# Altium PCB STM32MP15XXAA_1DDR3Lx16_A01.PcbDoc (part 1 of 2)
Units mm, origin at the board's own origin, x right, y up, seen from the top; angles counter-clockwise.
Board outline 86 x 120 mm, 6 copper layers (Top Layer, Signal Layer 1, Signal Layer 2, Signal Layer 3, Signal Layer 4, Bottom Layer), stack 1.556 mm thick; 100 components, 91 nets, 936 pads, 390 vias.
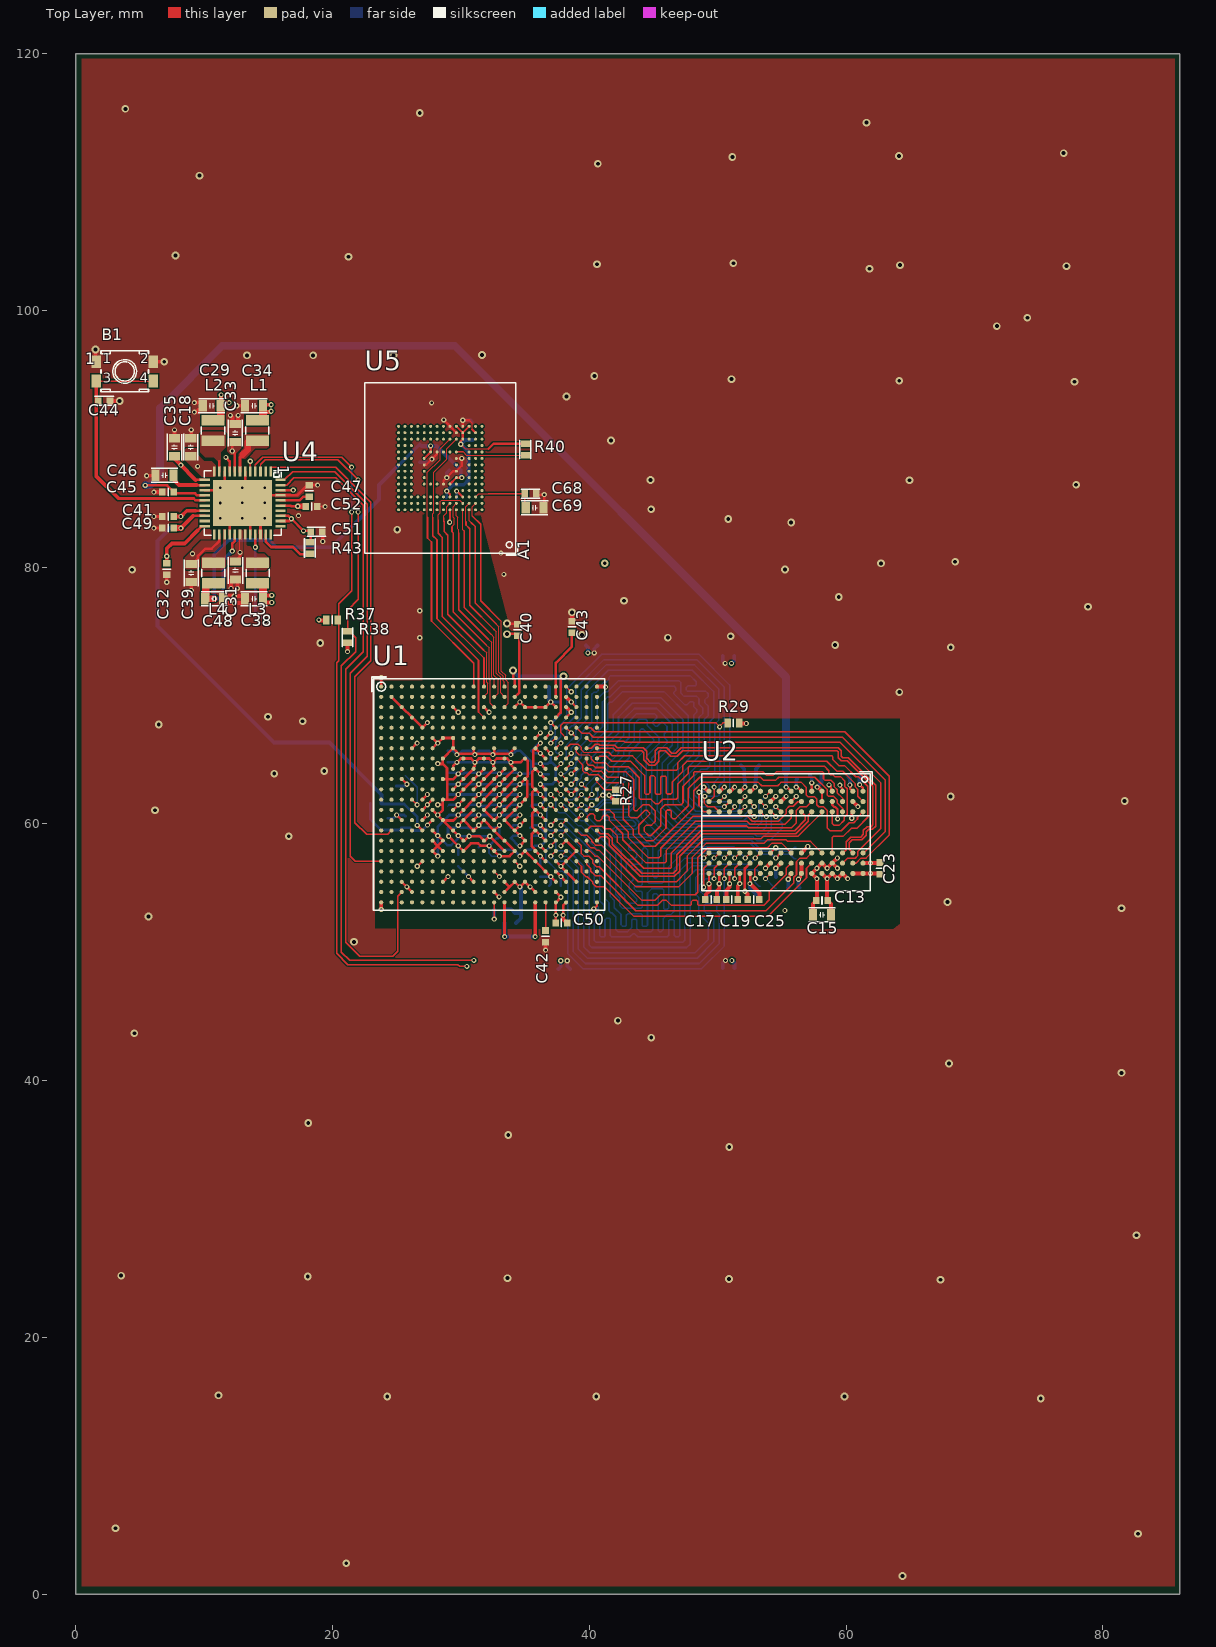
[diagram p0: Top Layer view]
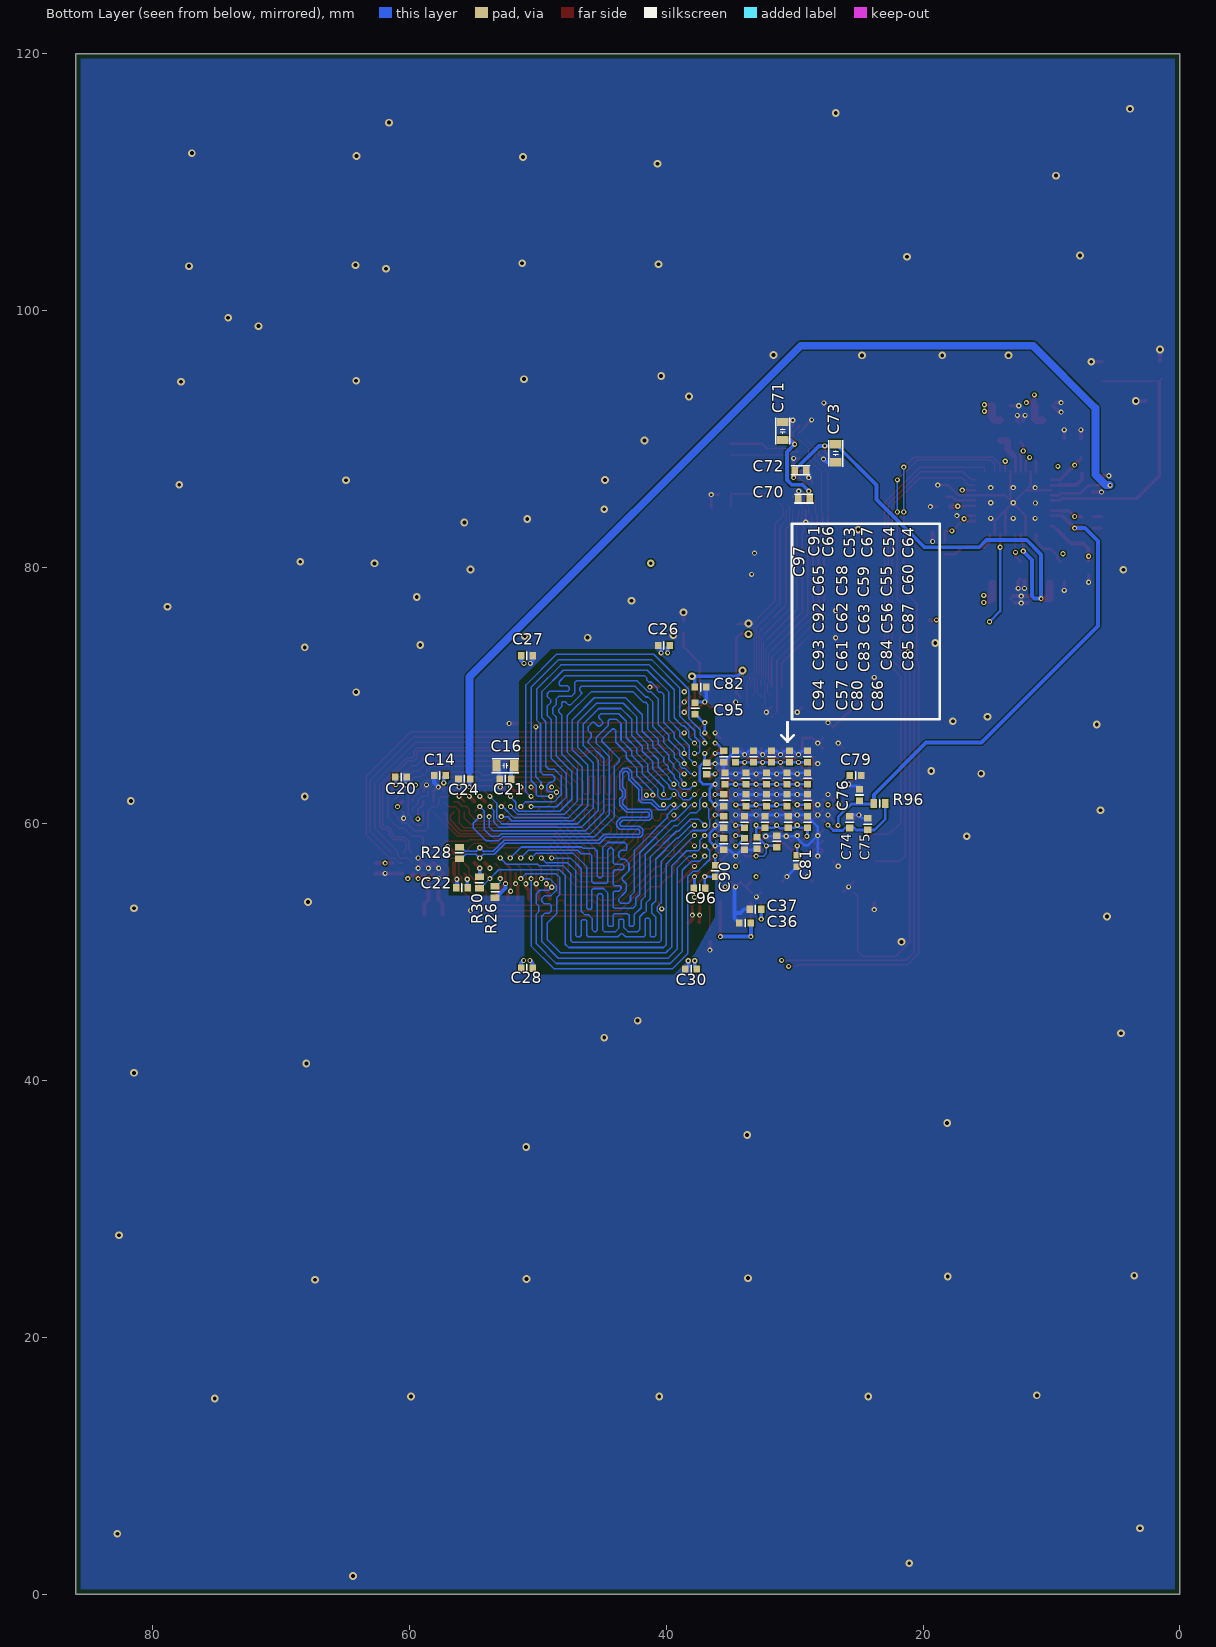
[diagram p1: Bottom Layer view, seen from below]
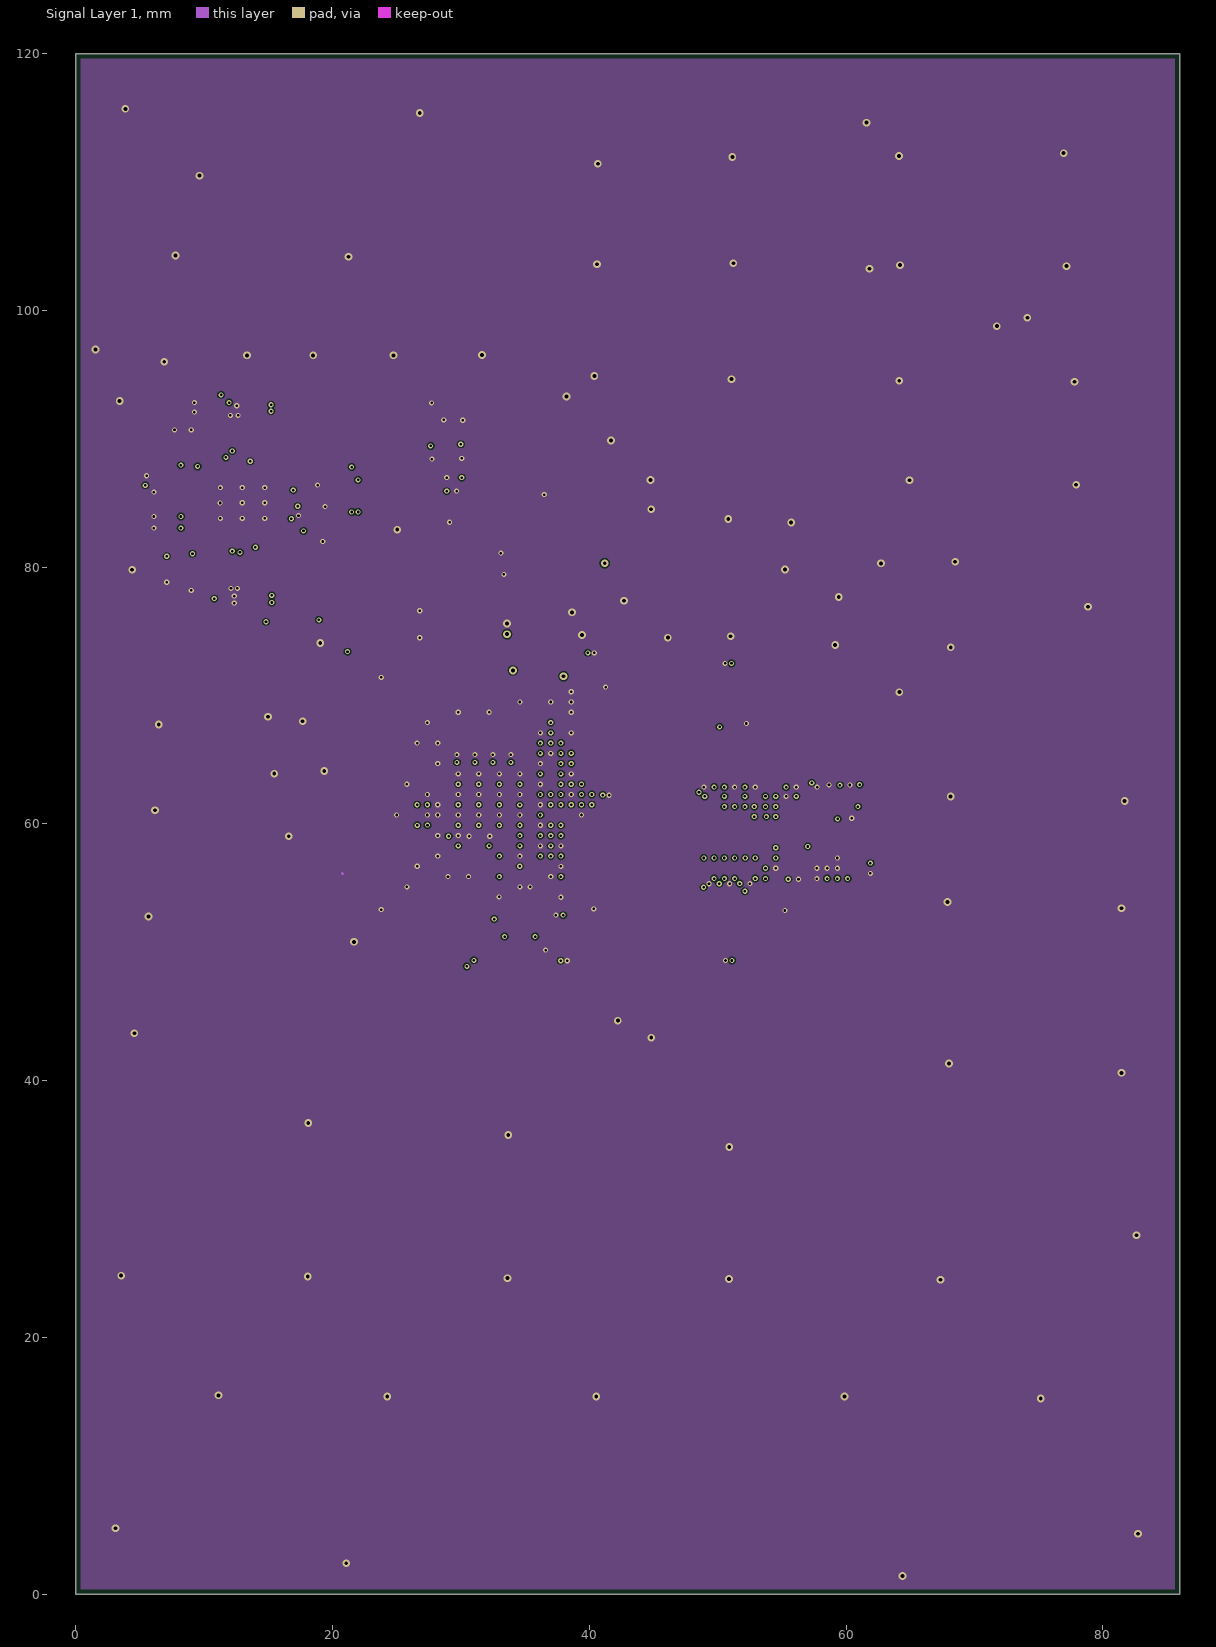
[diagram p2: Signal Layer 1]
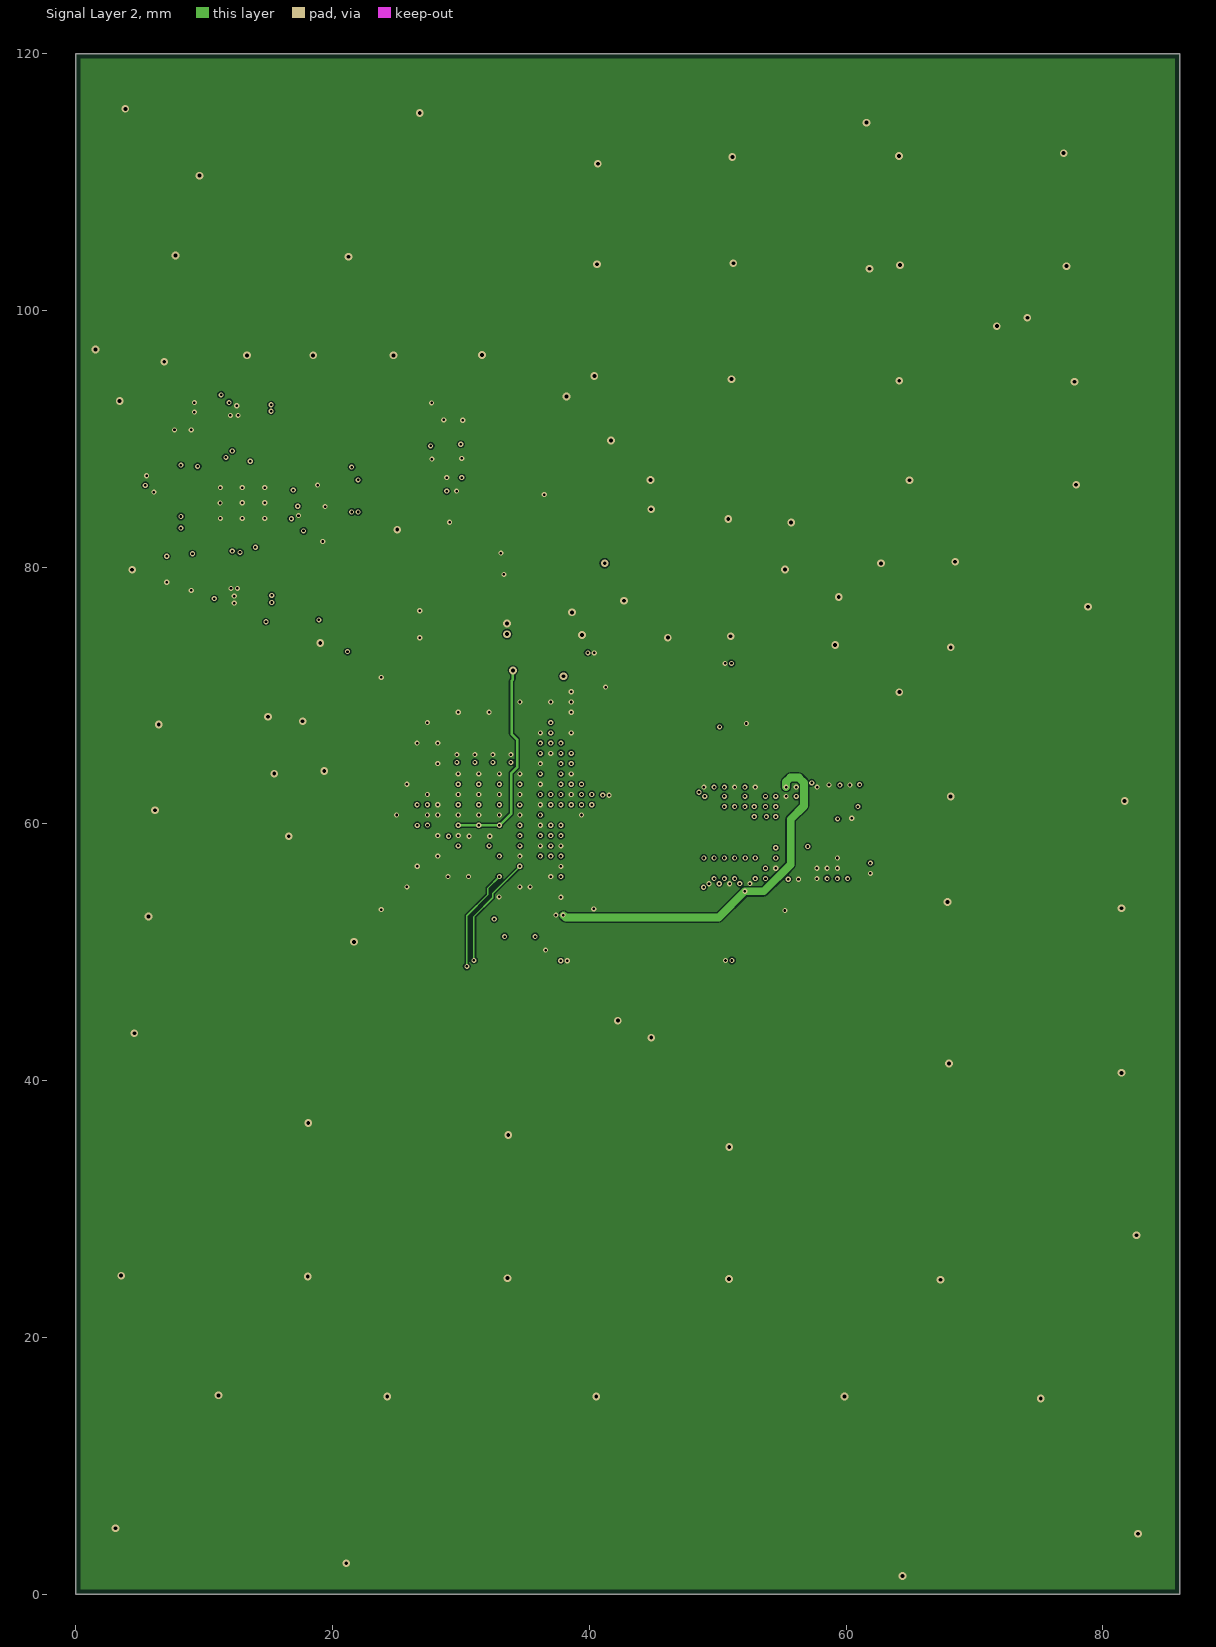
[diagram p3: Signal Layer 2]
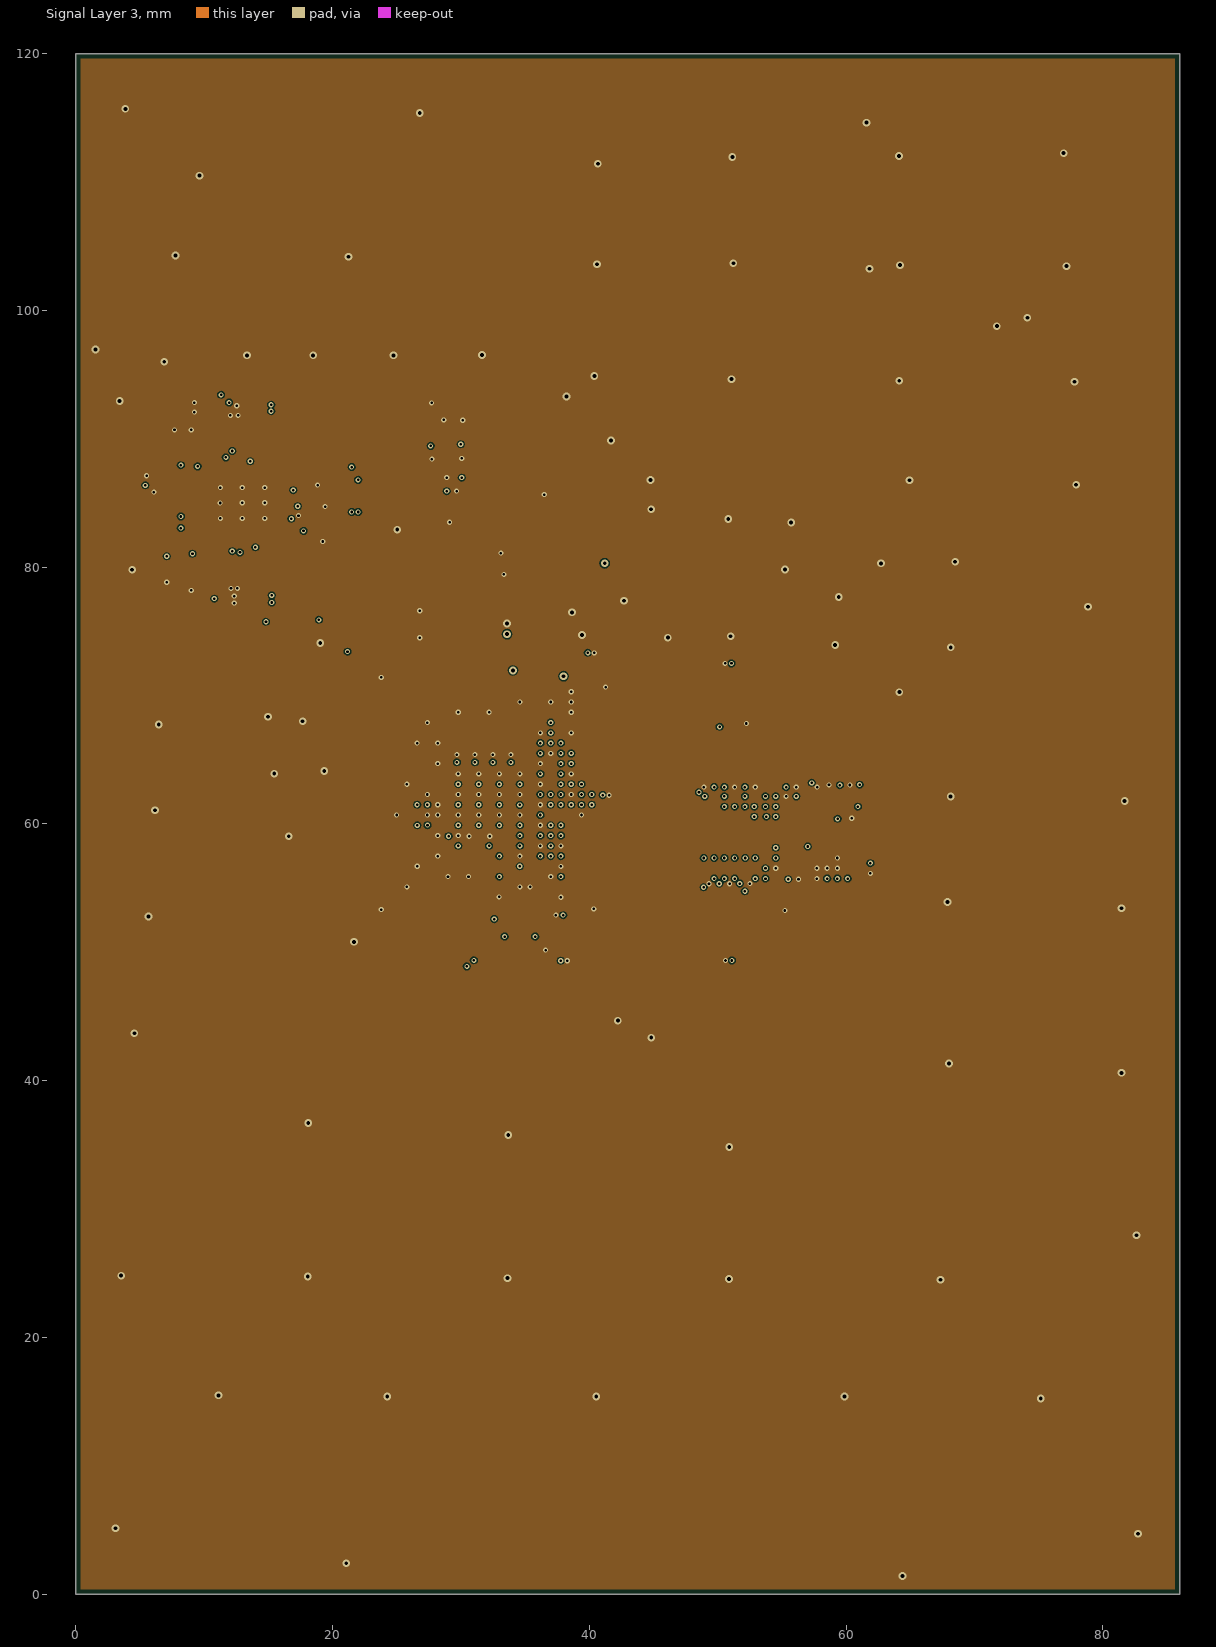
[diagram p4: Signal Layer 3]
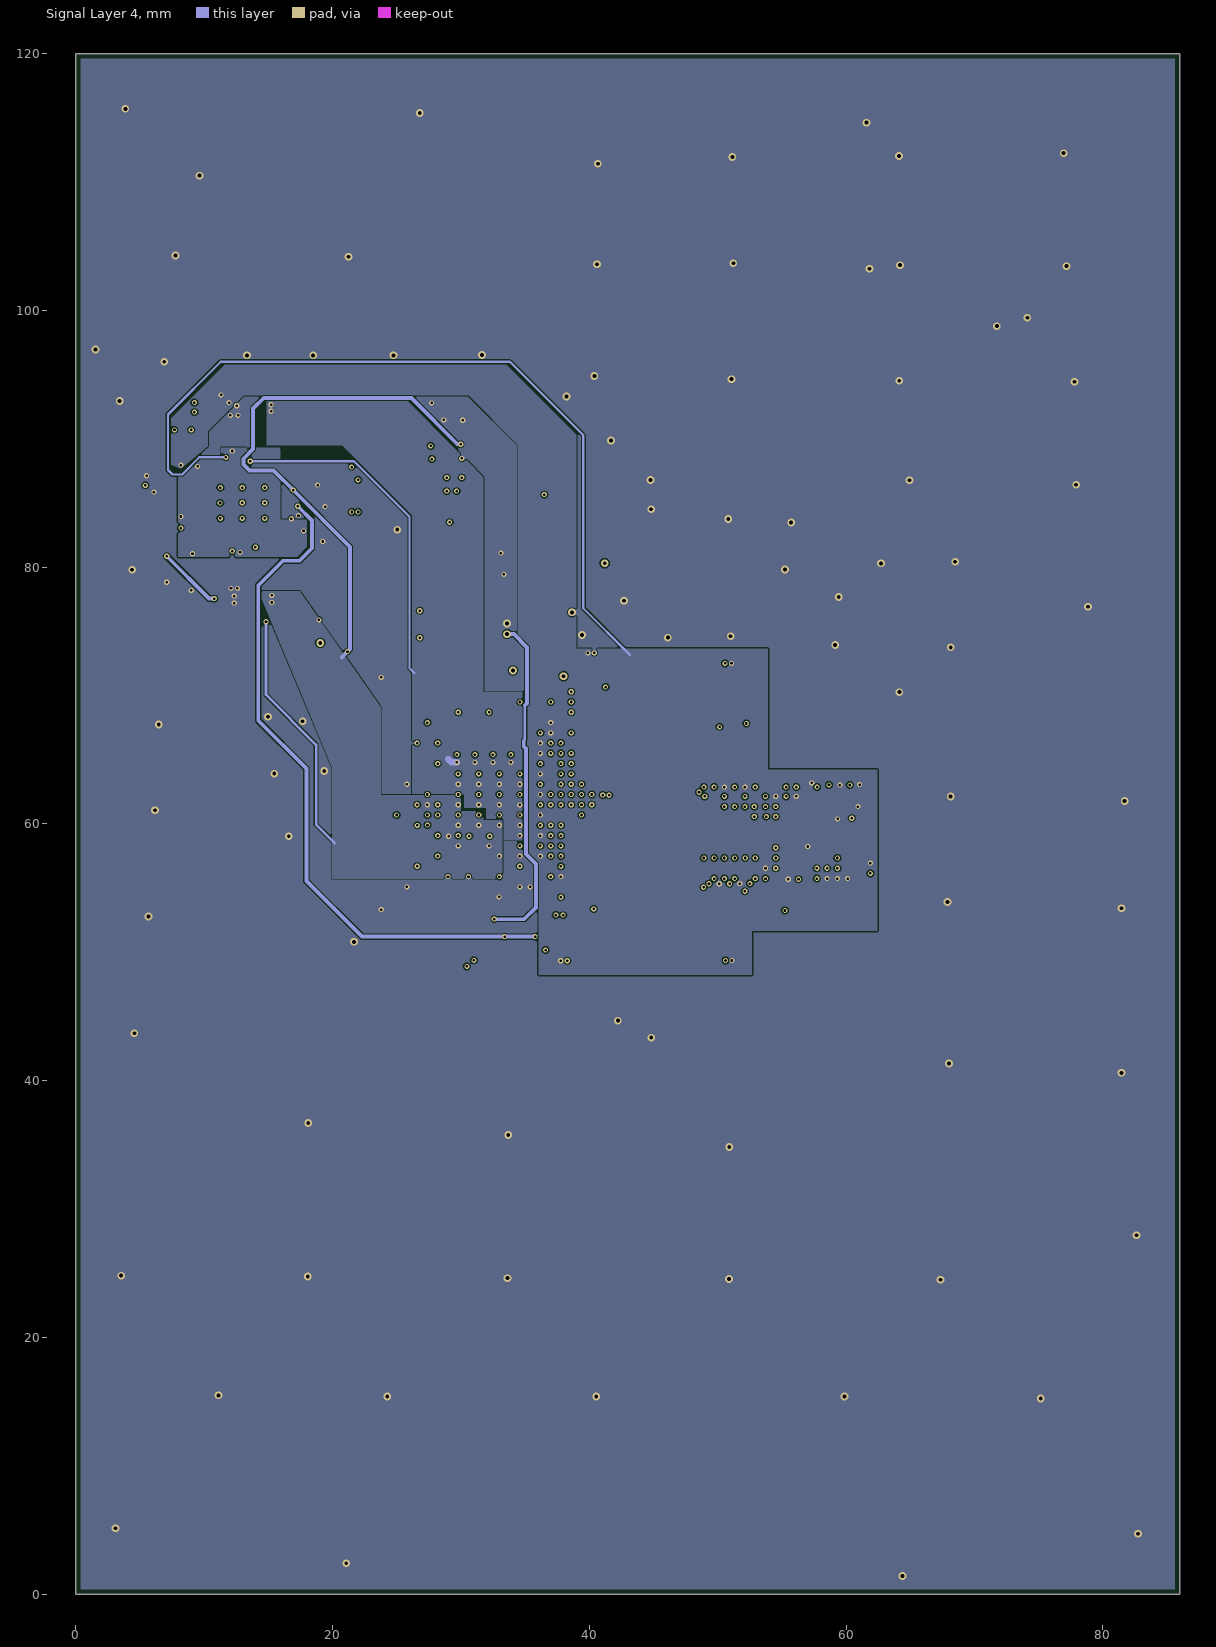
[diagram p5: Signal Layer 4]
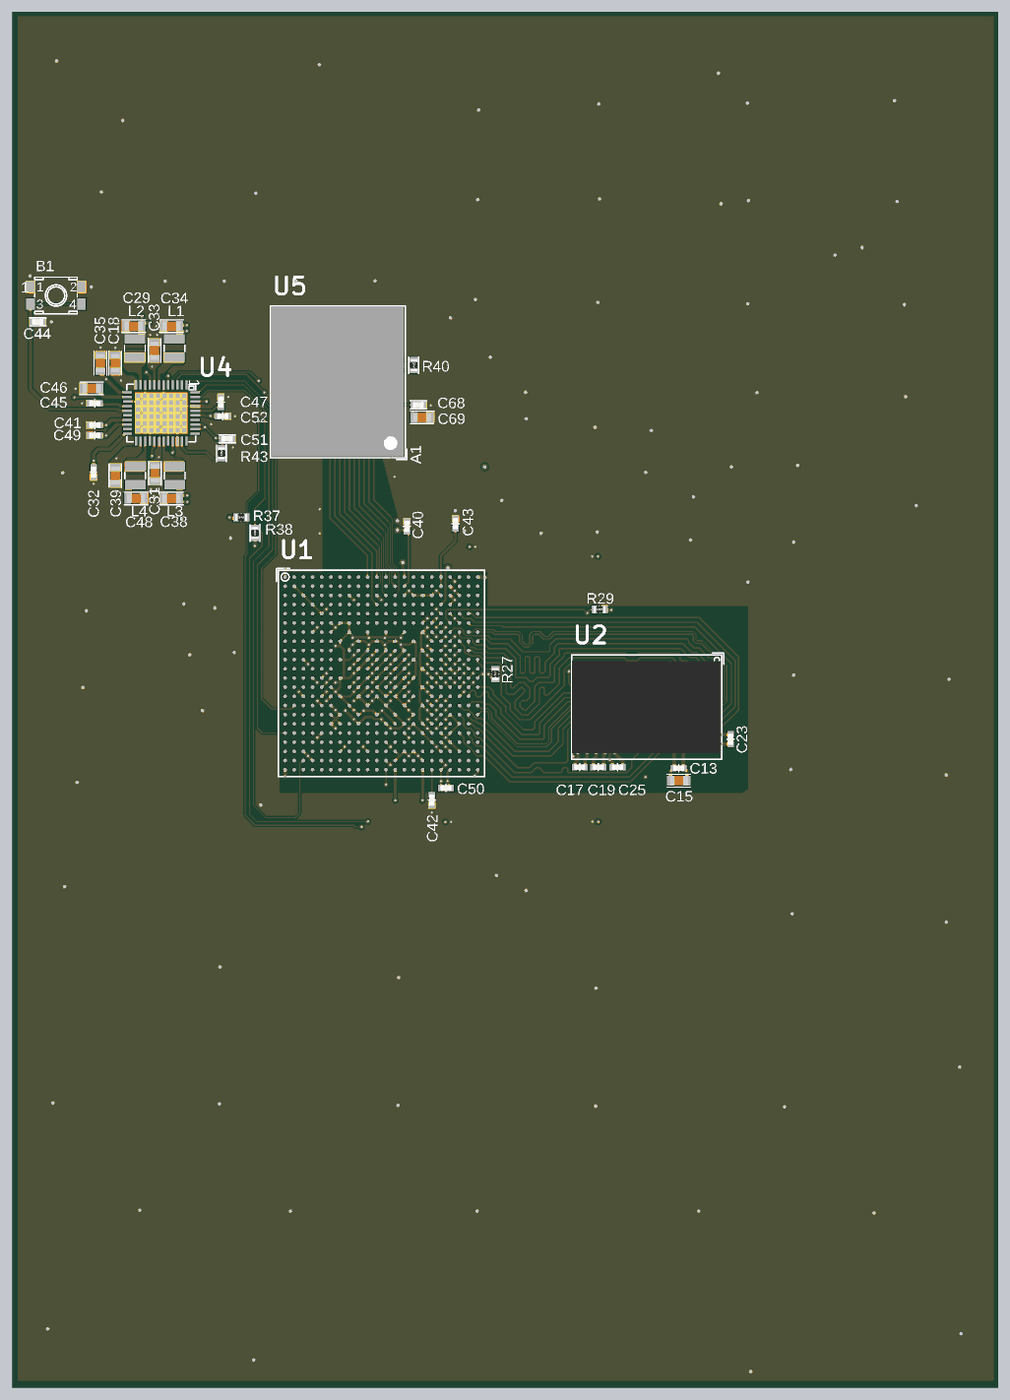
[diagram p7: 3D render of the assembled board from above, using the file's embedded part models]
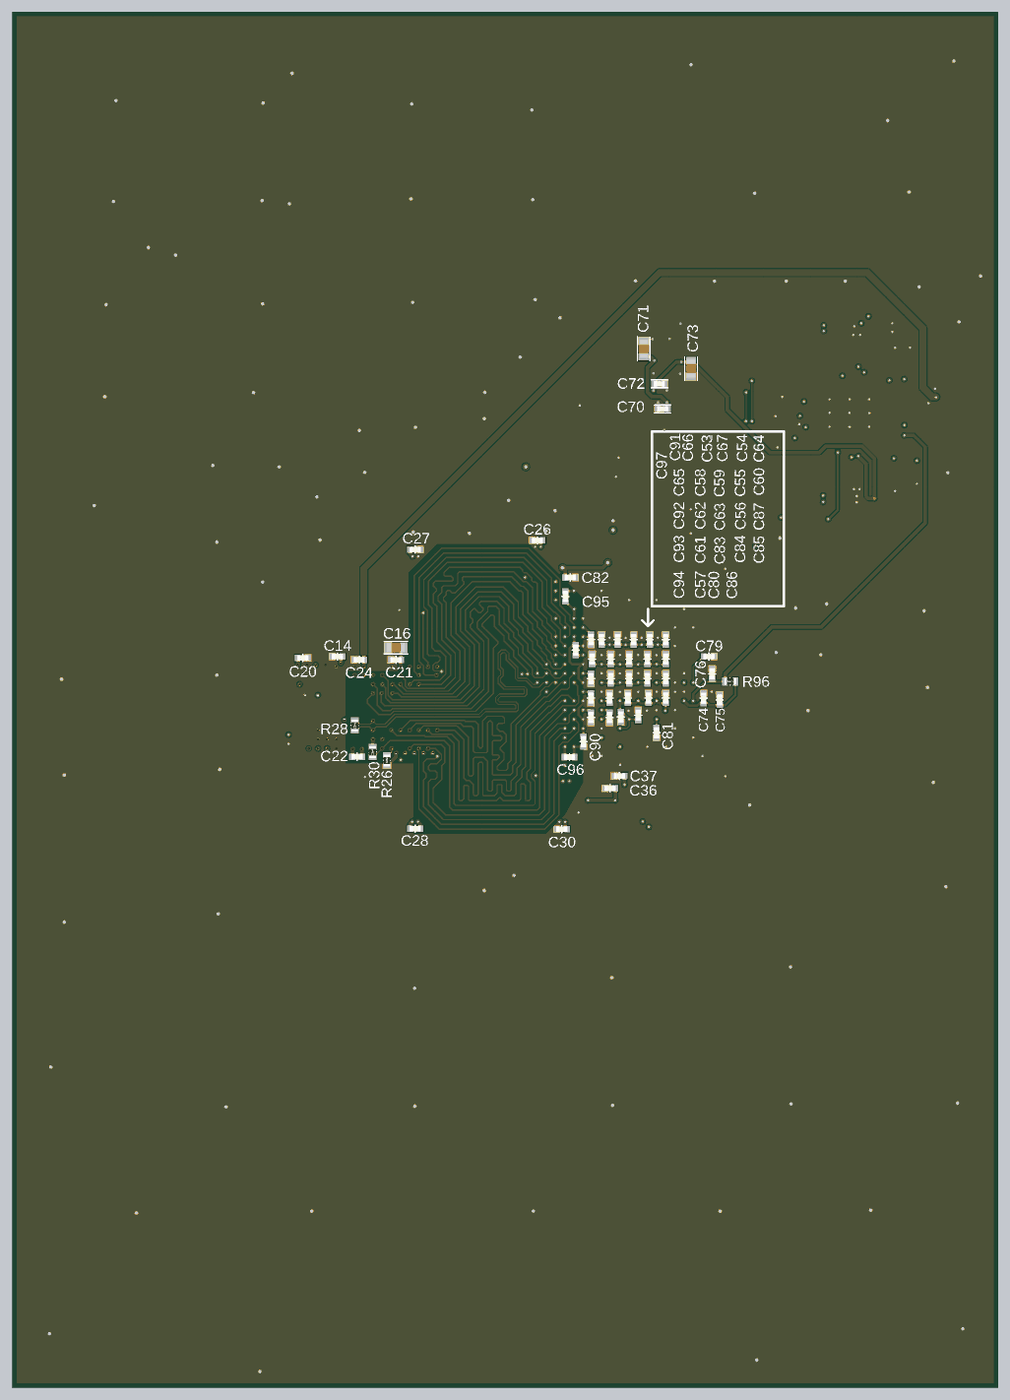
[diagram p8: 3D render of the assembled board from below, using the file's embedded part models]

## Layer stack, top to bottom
Top Solder: solder mask 0.0203, Solder Resist, Dk 3.5
Top Layer: signal copper 0.037
Dielectric 1: core 0.0986, FR-4, Dk 4.1
Signal Layer 1: signal copper 0.035
Dielectric 2: prepreg 0.13, FR-4, Dk 4.25
Signal Layer 2: signal copper 0.035
Dielectric 3: core 0.885, Dk 4.25
Signal Layer 3: signal copper 0.035
Dielectric 4: prepreg 0.13, Dk 4.25
Signal Layer 4: signal copper 0.035
Dielectric 5: core 0.0986, FR-4, Dk 4.1
Bottom Layer: signal copper 0.037
Bottom Solder: solder mask 0.0203, Solder Resist, Dk 3.5

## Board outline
0,0 0,120 86,120 86,0

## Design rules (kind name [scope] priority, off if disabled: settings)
BoardOutlineClearance [All] p1: gap=0.4 ignorepadtopadclearanceinfootprint=FALSE
Clearance diff [InNetClass('diff')] p1: gap=0.1 ignorepadtopadclearanceinfootprint=FALSE except(0: Arc-Hole Track-Hole SMDPad-Hole THPad-Hole Via-Hole Fill-Hole Poly-Hole Region-Hole Text-Hole; 0.08: Track-SMDPad; 0.13: Track-Track; 0.15: Arc-Fill Track-Fill SMDPad-Fill THPad-Fill Via-Fill Fill-Fill; 0.2: Arc-THPad SMDPad-SMDPad SMDPad-THPad THPad-THPad)
Clearance [InNetClass('All Nets')] p2: gap=0.1 ignorepadtopadclearanceinfootprint=FALSE except(0: Arc-Hole Track-Hole SMDPad-Hole THPad-Hole Via-Hole Fill-Hole Poly-Hole Region-Hole Text-Hole; 0.09: Track-SMDPad; 0.15: Arc-Fill Track-Fill SMDPad-Fill THPad-Fill Via-Fill Fill-Fill)
ComponentClearance [All] p1 off: gap=0.025 collisioncheckmode=3 verticalgap=2540 showdistances=TRUE
DiffPairsRouting [All] p1: maxlimit=0.13 minlimit=0.13 mostfreqgap=0.13 toplayer_minwidth=0.09 toplayer_maxwidth=0.13 toplayer_prefwidth=0.1 midlayer1_minwidth=0.09 midlayer1_maxwidth=0.13 midlayer1_prefwidth=0.1 midlayer2_minwidth=0.09 midlayer2_maxwidth=0.13 midlayer2_prefwidth=0.1 midlayer3_minwidth=0.09 midlayer3_maxwidth=0.13 midlayer3_prefwidth=0.1 midlayer4_minwidth=0.09 midlayer4_maxwidth=0.13 midlayer4_prefwidth=0.1 bottomlayer_minwidth=0.09 bottomlayer_maxwidth=0.13 bottomlayer_prefwidth=0.1 maxuncoupledlength=0.5
FanoutControl Fanout_BGA [IsBGA] p1: bgadir=Out bgaviamode=Closest fanoutstyle=Auto fanoutdirection=Alternating viagrid=0.025 // Fanout_BGA (Default Rule)
FanoutControl Fanout_LCC [IsLCC] p2: bgadir=Out bgaviamode=Closest fanoutstyle=Auto fanoutdirection=Alternating viagrid=0.025 // Fanout_LCC (Default Rule)
FanoutControl Fanout_SOIC [IsSOIC] p3: bgadir=Out bgaviamode=Closest fanoutstyle=Auto fanoutdirection=Alternating viagrid=0.025 // Fanout_SOIC (Default Rule)
FanoutControl Fanout_Small [(CompPinCount < 5)] p4: bgadir=Out bgaviamode=Closest fanoutstyle=Auto fanoutdirection=OutThenIn viagrid=0.025 // Fanout_Small (Default Rule)
FanoutControl Fanout_Default [All] p5: bgadir=Out bgaviamode=Closest fanoutstyle=Auto fanoutdirection=Alternating viagrid=0.025 // Fanout_Default (Default Rule)
Height [All] p1 off: minheight=0 maxheight=100 prefheight=0.5
HoleSize [All] p1: absolutevalues=TRUE maxlimit=10 minlimit=0.15 maxpercent=80.000 minpercent=20.000
HoleToHoleClearance [All] p1: gap=0.25 allowstackedmicrovias=TRUE
Length Length_SDMMC1 [InNetClass('NETC_SDMMC1')] p1: maxlimit=86 minlimit=81
MinimumSolderMaskSliver [All] p1: minsoldermaskwidth=0
PlaneClearance [All] p1: clearance=0.6
PlaneConnect [All] p1: planeconnectstyle=Direct reliefexpansion=0.508 reliefentries=4 reliefconductorwidth=0.254 reliefairgap=0.254
PolygonConnect [All] p1: connectstyle=Direct reliefconductorwidth=0.254 reliefentries=4 polygonreliefangle="90 Angle" airgapwidth=0.254
RoomDefinition U_STM32_MPU_IOs [InComponentClass('U_STM32_MPU_IOs')] p1 off: confinementstyle=ConfineIn formatcopy=TRUE lockcomponents=FALSE outline 104.55,11.05 155.35,11.05 155.35,36.45 104.55,36.45
RoomDefinition U_Power_MPU [InComponentClass('U_Power_MPU')] p2 off: confinementstyle=ConfineIn formatcopy=TRUE lockcomponents=FALSE outline 87.674,18.025 101.45,18.025 101.45,24 87.674,24
RoomDefinition U_eMMC [InComponentClass('U_eMMC')] p3 off: confinementstyle=ConfineIn formatcopy=TRUE lockcomponents=FALSE outline 87.122,1.416 129.449,1.416 129.449,15.666 87.122,15.666
RoomDefinition U_1DDR3L_16bits [InComponentClass('U_1DDR3L_16bits')] p4 off: confinementstyle=ConfineIn formatcopy=TRUE lockcomponents=FALSE outline 92.5,18.4 143.3,18.4 143.3,43.8 92.5,43.8
RoomDefinition U_Power_PMIC [InComponentClass('U_Power_PMIC')] p5 off: confinementstyle=ConfineIn formatcopy=TRUE lockcomponents=FALSE outline 87.122,8.666 203.578,8.666 203.578,17.666 87.122,17.666
RoutingVias RoutingVias_GND [InNetClass('GND')] p1: holewidth=0.3 width=0.6 viastyle="Through Hole" minholewidth=0.2 minwidth=0.4 maxholewidth=0.3 maxwidth=0.6
RoutingVias RoutingVias_ALIMS [InNetClass('ALIMS')] p2: holewidth=0.3 width=0.6 viastyle="Through Hole" minholewidth=0.2 minwidth=0.4 maxholewidth=0.3 maxwidth=0.6
RoutingVias [All] p3: holewidth=0.2 width=0.4 viastyle="Through Hole" minholewidth=0.2 minwidth=0.4 maxholewidth=0.3 maxwidth=0.6
SilkToSilkClearance [All] p1: silktosilkclearance=0
SilkToSolderMaskClearance [IsPad] p1: minsilkscreentomaskgap=0 clearancetoexposedcopper=TRUE
SolderMaskExpansion [All] p1: expansion=0.05 istentingtop=FALSE
Width VDD_DDR [InNet('VDD_DDR')] p1: maxlimit=0.6 minlimit=0.1 preferedwidth=0.3
Width Width_VCORE [InNet('VDD_CORE')] p2: maxlimit=0.6 minlimit=0.15 preferedwidth=0.3 midlayer1_minwidth=0.175 midlayer2_minwidth=0.175 midlayer3_minwidth=0.175 midlayer4_minwidth=0.175 bottomlayer_minwidth=0.175 minimp=50.000000 maximp=50.000000 favimp=50.000000
Width Width_gnd [InNet('GND')] p3: maxlimit=0.3 minlimit=0.09 preferedwidth=0.3 midlayer1_minwidth=0.1 midlayer2_minwidth=0.1 midlayer3_minwidth=0.1 midlayer4_minwidth=0.1 bottomlayer_minwidth=0.1 minimp=50.000000 maximp=50.000000 favimp=50.000000
Width [All] p4: maxlimit=0.6 minlimit=0.09 preferedwidth=0.12 midlayer1_minwidth=0.1 midlayer2_minwidth=0.1 midlayer3_minwidth=0.1 midlayer4_minwidth=0.1 bottomlayer_minwidth=0.1 minimp=50.000000 maximp=50.000000 favimp=50.000000
15 further rules are at their usual default settings.

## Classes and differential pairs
net class eMMC_SDIO2_D[0..7]: eMMC_SDIO2_D0 eMMC_SDIO2_D1 eMMC_SDIO2_D2 eMMC_SDIO2_D3 eMMC_SDIO2_D4 eMMC_SDIO2_D5 eMMC_SDIO2_D6 eMMC_SDIO2_D7
component class U_STM32_MPU_IOs: C50 R27 R37 R38 U1
component class U_eMMC: C68 C69 C70 C71 C72 C73 R40 U5
component class U_Power_PMIC: B1 C18 C29 C31 C32 C33 C34 C35 C38 C39 C41 C44 C45 C46 C47 C48 C49 C51 C52 L1 L2 L3 L4 R43 U4
component class U_Power_MPU: C36 C37 C40 C42 C43 C53 C54 C55 C56 C57 C58 C59 C60 C61 C62 C63 C64 C65 C66 C67 C74 C75 C76 C79 C80 C81 C82 C83 C84 C85 C86 C87 C90 C91 C92 C93 C94 C95 C96 C97 R96
component class U_1DDR3L_16bits: C13 C14 C15 C16 C17 C19 C20 C21 C22 C23 C24 C25 C26 C27 C28 C30 R26 R28 R29 R30 U2
polygon class POLY_DIRECT_ALL: NETC906_2_L01_P192
differential pair class DIFF_DQS0: DDR_DQS0
differential pair class DIFF_DQS1: DDR_DQS1
differential pair class DIFF_CLK: DDR_CLK
from-to class DDR_DQ: "DDR_DQ0 (U2-B8 : U1-A17)" "DDR_DQ1 (U2-A7 : U1-A18)" "DDR_DQ2 (U1-D18 : U2-C2)" "DDR_DQ3 (U1-B17 : U2-C8)" "DDR_DQ4 (U2-A3 : U1-E18)" "DDR_DQ5 (U1-D17 : U2-C3)" "DDR_DQ6 (U2-A2 : U1-D19)" "DDR_DQ7 (U1-B18 : U2-D7)" "DDR_DQ8 (U1-P18 : U2-G2)" "DDR_DQ9 (U2-E3 : U1-T17)" "DDR_DQ10 (U1-R18 : U2-H3)" "DDR_DQ11 (U2-H8 : U1-V19)" "DDR_DQ12 (U1-W18 : U2-F8)" "DDR_DQ13 (U2-F2 : U1-T18)" "DDR_DQ14 (U1-V18 : U2-H7)" "DDR_DQ15 (U2-F7 : U1-W17)" "DDR_DQM0 (U1-C18 : U2-D3)" "DDR_DQM1 (U2-E7 : U1-U18)" "DDR_DQS0_N (U1-B19 : U2-B7)" "DDR_DQS0_P (U2-C7 : U1-C19)" "DDR_DQS1_N (U1-T19 : U2-G3)" "DDR_DQS1_P (U2-F3 : U1-U19)"
from-to class ddr_addr_ctrl: "DDR_A0 (U1-H18 : U2-N3)" "DDR_A1 (U2-P7 : U1-M17)" "DDR_A2 (U1-G18 : U2-P3)" "DDR_A3 (U1-F19 : U2-N2)" "DDR_A4 (U2-P8 : U1-P17)" "DDR_A5 (U1-H17 : U2-P2)" "DDR_A6 (U1-N16 : U2-R8)" "DDR_A7 (U2-R2 : U1-E17)" "DDR_A8 (U1-R17 : U2-T8)" "DDR_A9 (U2-R3 : U1-G17)" "DDR_A10 (U1-M19 : U2-L7)" "DDR_A11 (U2-R7 : U1-M18)" "DDR_A12 (U1-L17 : U2-N7)" "DDR_A13 (U1-F17 : U2-T3)" "DDR_A14 (U2-T7 : U1-N18)" "DDR_A15 (U2-M7 : U1-L16)" "DDR_BA0 (U2-M2 : U1-G19)" "DDR_BA1 (U1-N17 : U2-N8)" "DDR_BA2 (U2-M3 : U1-J16)" "DDR_CASN (U1-K17 : U2-K3)" "DDR_CKE (U2-K9 : U1-P19)" "DDR_CLK_N (U2-K7 : U1-K19)" "DDR_CLK_P (U2-J7 : U1-L19)" "DDR_CSN (U1-J18 : U2-L2)" "DDR_ODT (U1-H19 : U2-K1)" "DDR_RASN (U1-L18 : U2-J3)" "DDR_WEN (U1-J17 : U2-L3)"
differential pair DDR_DQS1: +DDR_DQS1_P -DDR_DQS1_N
differential pair DDR_DQS0: +DDR_DQS0_P -DDR_DQS0_N

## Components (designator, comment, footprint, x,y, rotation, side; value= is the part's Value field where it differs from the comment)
B1 "SW-PUSH-TS-02H-Blue" SWI_JIUBABA_C-TS-02H-2-5-B-V-T_R_BLUE 3.825,95.25 r0 top
C13 "Capacitor" C0402#1 58.13,54.035 r0 top
C14 "Capacitor" C0402#1 57.635,63.775 r180 bottom
C15 "Capacitor" C0603#1 58.135,52.94 r0 top
C16 "Capacitor" C0603#1 52.53,64.545 r180 bottom
C17 "Capacitor" C0402#1 49.5,54.12 r0 top
C18 "Capacitor" C0603#2 8.975,89.35 r270 bottom
C19 "Capacitor" C0402#1 51.115,54.12 r0 top
C20 "Capacitor" C0402#1 60.65,63.65 r0 bottom
C21 "Capacitor" C0402#1 52.53,63.48 r180 bottom
C22 "Capacitor" C0402#1 55.92,55.03 r0 bottom
C23 "Capacitor" C0402#1 62.645,56.55 r90 top
C24 "Capacitor" C0402#1 55.73,63.495 r180 bottom
C25 "Capacitor" C0402#1 52.8,54.12 r180 top
C26 "Capacitor" C0402#1 40.19,73.895 r180 bottom
C27 "Capacitor" C0402#1 50.85,73.1 r0 bottom
C28 "Capacitor" C0402#1 50.85,48.76 r0 bottom
C29 "Capacitor" C0603#2 10.6,92.575 r0 bottom
C30 "Capacitor" C0402#1 38.07,48.715 r180 bottom
C31 "Capacitor" C0603#2 12.45,79.75 r90 bottom
C32 "Capacitor" C0402#2 7.1,79.85 r90 bottom
C33 "Capacitor" C0603#2 12.425,90.45 r270 bottom
C34 "Capacitor" C0603#2 13.9,92.575 r0 bottom
C35 "Capacitor" C0603#2 7.7,89.35 r270 bottom
C36 "Capacitor" C0402#1 33.855,52.285 r180 bottom
C37 "Capacitor" C0402#1 33.05,53.36 r180 bottom
C38 "Capacitor" C0603#2 13.9,77.55 r0 bottom
C39 "Capacitor" C0603#2 9,79.55 r90 bottom
C40 "Capacitor" C0402#1 34.425,75.115 r270 top
C41 "Capacitor" C0402#2 7.2,83.95 r0 bottom
C42 "Capacitor" C0402#1 36.6,51.255 r90 top
C43 "Capacitor" C0402#1 38.66,75.35 r270 top
C44 "Capacitor" C0402#1 2.225,92.95 r180 top
C45 "Capacitor" C0402#1 7.2,85.85 r0 top
C46 "Capacitor" C0603#1 6.925,87.15 r0 top
C47 "Capacitor" C0402#2 18.2,85.95 r270 bottom
C48 "Capacitor" C0603#2 10.8,77.55 r180 bottom
C49 "Capacitor" C0402#2 7.2,83.05 r0 bottom
C50 "Capacitor" C0402#1 37.83,52.3 r0 top
C51 "Capacitor" C0402#1 18.75,82.75 r0 top
C52 "Capacitor" C0402#1 18.375,84.725 r180 top
C53 "Capacitor" C0402#1 33.2,65.25 r270 bottom
C54 "Capacitor" C0402#1 30.4,65.25 r270 bottom
C55 "Capacitor" C0402#1 30.6,63.55 r270 bottom
C56 "Capacitor" C0402#1 30.6,61.85 r270 bottom
C57 "Capacitor" C0402#1 33.9,58.45 r90 bottom
C58 "Capacitor" C0402#1 33.8,63.55 r270 bottom
C59 "Capacitor" C0402#1 32.2,63.55 r270 bottom
C60 "Capacitor" C0402#1 29,63.55 r270 bottom
C61 "Capacitor" C0402#1 33.9,60.15 r270 bottom
C62 "Capacitor" C0402#1 33.8,61.85 r270 bottom
C63 "Capacitor" C0402#1 32.2,61.85 r270 bottom
C64 "Capacitor" C0402#1 29,65.25 r270 bottom
C65 "Capacitor" C0402#1 35.425,63.55 r270 bottom
C66 "Capacitor" C0402#1 34.6,65.25 r270 bottom
C67 "Capacitor" C0402#1 31.8,65.25 r270 bottom
C68 "Capacitor" C0402#1 35.425,85.725 r180 top
C69 "Capacitor" C0603#1 35.75,84.625 r180 top
C70 "Capacitor" C0402#1 29.275,85.35 r180 bottom
C71 "Capacitor" C0603#1 30.925,90.6 r270 bottom
C72 "Capacitor" C0402#1 29.55,87.55 r0 bottom
C73 "Capacitor" C0603#1 26.8,88.875 r90 bottom
C74 "Capacitor" C0402#1 25.705,60.14 r270 bottom
C75 "Capacitor" C0402#1 24.305,59.985 r270 bottom
C76 "Capacitor" C0402#1 24.955,62.26 r270 bottom
C79 "Capacitor" C0402#1 25.245,63.77 r0 bottom
C80 "Capacitor" C0402#1 32.925,58.505 r90 bottom
C81 "Capacitor" C0402#1 29.805,57.12 r90 bottom
C82 "Capacitor" C0402#1 37.33,70.66 r0 bottom
C83 "Capacitor" C0402#1 32.3,60.15 r270 bottom
C84 "Capacitor" C0402#1 30.5,60.15 r270 bottom
C85 "Capacitor" C0402#1 29,60.15 r270 bottom
C86 "Capacitor" C0402#1 31.4,58.65 r270 bottom
C87 "Capacitor" C0402#1 29,61.85 r270 bottom
C90 "Capacitor" C0402#1 36.175,56.35 r90 bottom
C91 "Capacitor" C0402#1 35.52,65.25 r90 bottom
C92 "Capacitor" C0402#1 35.52,61.85 r90 bottom
C93 "Capacitor" C0402#1 35.52,60.15 r90 bottom
C94 "Capacitor" C0402#1 35.52,58.45 r90 bottom
C95 "Capacitor" C0402#1 37.75,69 r270 bottom
C96 "Capacitor" C0402#1 37.4,55 r0 bottom
C97 "Capacitor" C0402#1 36.85,64.325 r270 bottom
L1 "Inductor" IND_MURATA_DFE201612P 14.15,90.65 r90 bottom
L2 "Inductor" IND_MURATA_DFE201612P 10.7,90.65 r90 bottom
L3 "Inductor" IND_MURATA_DFE201612P 14.175,79.55 r270 bottom
L4 "Inductor" IND_MURATA_DFE201612P 10.725,79.55 r270 bottom
R26 "Resistor" R0402#1 53.325,54.71 r90 bottom
R27 "Resistor" R0402#1 42.14,62.235 r270 top
R28 "Resistor" R0402#1 56.12,57.755 r270 bottom
R29 "Resistor" R0402#1 51.225,67.87 r180 top
R30 "Resistor" R0402#1 54.56,55.435 r270 bottom
R37 "Resistor" R0402#1 19.975,75.9 r0 top
R38 "Resistor" R0402#1 21.175,74.55 r90 top
R40 "Resistor" R0402#1 35.025,89.175 r90 top
R43 "Resistor" R0402#2 18.25,81.5 r90 bottom
R96 "Resistor" R0402#1 23.38,61.595 r180 bottom
U1 "STM32MP157BAA3" ICC_LFBGA448_18X18_STM32MP157BAA3_P080 32.2,62.3 r0 top locked
U2 "NT5CC256M16ER-EK" ICC_VFBGA96_9x13_P080 55.33,59.35 r270 top locked
U4 "STPMU1" ICC_WFQFN44-EPAD_5X6_P040 13,85 r270 top
U5 "eMMC_THGBMDG5D1LBAIL" ICC_P-WFBGA153_13X11P5_P050 28.4,87.725 r90 top locked

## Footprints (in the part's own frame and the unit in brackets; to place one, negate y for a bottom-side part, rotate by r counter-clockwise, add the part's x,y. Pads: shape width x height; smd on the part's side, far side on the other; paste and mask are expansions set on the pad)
C0402#1 [mm]
  rect 0.51x0.56 smd mask+0.05: 1(-0.45,0) 2(0.45,0)
  silkscreen extent 0,-0.3 0,0.3, body extent -0.5,-0.3 0.5,0.3, height 0.4
C0402#2 [mm]
  rect 0.51x0.56 smd far side mask+0.05: 1(-0.45,0) 2(0.45,0)
  body extent -0.5,-0.3 0.5,0.3, height 0.4
C0603#1 [mm]
  rect 0.64x0.89 smd mask+0.05: 1(-0.7,0) 2(0.7,0)
  silkscreen extent -1.05,-0.55 1.02,0.55, body extent -0.9,-0.5 0.9,0.5, height 1.4
C0603#2 [mm]
  rect 0.64x0.89 smd far side mask+0.05: 1(-0.7,0) 2(0.7,0)
  body extent -0.9,-0.5 0.9,0.5, height 1.4
ICC_LFBGA448_18X18_STM32MP157BAA3_P080 [mm] "IPC"
  round 0.32 smd mask+0.05: A1(-8.4,8.4) A2(-7.6,8.4) A3(-6.8,8.4) A4(-6,8.4) A5(-5.2,8.4) A6(-4.4,8.4) A7(-3.6,8.4) A8(-2.8,8.4) A9(-2,8.4) A10(-1.2,8.4) A11(-0.4,8.4) A12(0.4,8.4) A13(1.2,8.4) A14(2,8.4) A15(2.8,8.4) A16(3.6,8.4) A17(4.4,8.4) A18(5.2,8.4) A19(6,8.4) A20(6.8,8.4) A21(7.6,8.4) A22(8.4,8.4) AA1(-8.4,-7.6) AA2(-7.6,-7.6) AA3(-6.8,-7.6) AA4(-6,-7.6) AA5(-5.2,-7.6) AA6(-4.4,-7.6) AA7(-3.6,-7.6) AA8(-2.8,-7.6) AA9(-2,-7.6) AA10(-1.2,-7.6) AA11(-0.4,-7.6) AA12(0.4,-7.6) AA13(1.2,-7.6) AA14(2,-7.6) AA15(2.8,-7.6) AA16(3.6,-7.6) AA17(4.4,-7.6) AA18(5.2,-7.6) AA19(6,-7.6) AA20(6.8,-7.6) AA21(7.6,-7.6) AA22(8.4,-7.6) AB1(-8.4,-8.4) AB2(-7.6,-8.4) AB3(-6.8,-8.4) AB4(-6,-8.4) AB5(-5.2,-8.4) AB6(-4.4,-8.4) AB7(-3.6,-8.4) AB8(-2.8,-8.4) AB9(-2,-8.4) AB10(-1.2,-8.4) AB11(-0.4,-8.4) AB12(0.4,-8.4) AB13(1.2,-8.4) AB14(2,-8.4) AB15(2.8,-8.4) AB16(3.6,-8.4) AB17(4.4,-8.4) AB18(5.2,-8.4) AB19(6,-8.4) AB20(6.8,-8.4) AB21(7.6,-8.4) AB22(8.4,-8.4) B1(-8.4,7.6) B2(-7.6,7.6) B3(-6.8,7.6) B4(-6,7.6) B5(-5.2,7.6) B6(-4.4,7.6) B7(-3.6,7.6) B8(-2.8,7.6) B9(-2,7.6) B10(-1.2,7.6) B11(-0.4,7.6) B12(0.4,7.6) B13(1.2,7.6) B14(2,7.6) B15(2.8,7.6) B16(3.6,7.6) B17(4.4,7.6) B18(5.2,7.6) B19(6,7.6) B20(6.8,7.6) B21(7.6,7.6) B22(8.4,7.6) C1(-8.4,6.8) C2(-7.6,6.8) C3(-6.8,6.8) C4(-6,6.8) C5(-5.2,6.8) C6(-4.4,6.8) C7(-3.6,6.8) C8(-2.8,6.8) C9(-2,6.8) C10(-1.2,6.8) C11(-0.4,6.8) C12(0.4,6.8) C13(1.2,6.8) C14(2,6.8) C15(2.8,6.8) C16(3.6,6.8) C17(4.4,6.8) C18(5.2,6.8) C19(6,6.8) C20(6.8,6.8) C21(7.6,6.8) C22(8.4,6.8) D1(-8.4,6) D2(-7.6,6) D3(-6.8,6) D4(-6,6) D5(-5.2,6) D6(-4.4,6) D7(-3.6,6) D8(-2.8,6) D9(-2,6) D10(-1.2,6) D11(-0.4,6) D12(0.4,6) D13(1.2,6) D14(2,6) D15(2.8,6) D16(3.6,6) D17(4.4,6) D18(5.2,6) D19(6,6) D20(6.8,6) D21(7.6,6) D22(8.4,6) E1(-8.4,5.2) E2(-7.6,5.2) E3(-6.8,5.2) E4(-6,5.2) E5(-5.2,5.2) E6(-4.4,5.2) E7(-3.6,5.2) E8(-2.8,5.2) E9(-2,5.2) E10(-1.2,5.2) E11(-0.4,5.2) E12(0.4,5.2) E13(1.2,5.2) E14(2,5.2) E15(2.8,5.2) E16(3.6,5.2) E17(4.4,5.2) E18(5.2,5.2) E19(6,5.2) E20(6.8,5.2) E21(7.6,5.2) E22(8.4,5.2) F1(-8.4,4.4) F2(-7.6,4.4) F3(-6.8,4.4) F4(-6,4.4) F5(-5.2,4.4) F6(-4.4,4.4) F7(-3.6,4.4) F8(-2.8,4.4) F9(-2,4.4) F10(-1.2,4.4) F11(-0.4,4.4) F12(0.4,4.4) F13(1.2,4.4) F14(2,4.4) F15(2.8,4.4) F16(3.6,4.4) F17(4.4,4.4) F18(5.2,4.4) F19(6,4.4) F20(6.8,4.4) F21(7.6,4.4) G1(-8.4,3.6) G2(-7.6,3.6) G3(-6.8,3.6) G4(-6,3.6) G5(-5.2,3.6) G6(-4.4,3.6) G8(-2.8,3.6) G10(-1.2,3.6) G12(0.4,3.6) G14(2,3.6) G16(3.6,3.6) G17(4.4,3.6) G18(5.2,3.6) G19(6,3.6) G20(6.8,3.6) G21(7.6,3.6) G22(8.4,3.6) H1(-8.4,2.8) H2(-7.6,2.8) H3(-6.8,2.8) H4(-6,2.8) H5(-5.2,2.8) H6(-4.4,2.8) H7(-3.6,2.8) H9(-2,2.8) H11(-0.4,2.8) H13(1.2,2.8) H15(2.8,2.8) H17(4.4,2.8) H18(5.2,2.8) H19(6,2.8) H20(6.8,2.8) H21(7.6,2.8) H22(8.4,2.8) J1(-8.4,2) J2(-7.6,2) J3(-6.8,2) J4(-6,2) J5(-5.2,2) J6(-4.4,2) J8(-2.8,2) J9(-2,2) J10(-1.2,2) J11(-0.4,2) J12(0.4,2) J13(1.2,2) J14(2,2) J16(3.6,2) J17(4.4,2) J18(5.2,2) J19(6,2) J20(6.8,2) J21(7.6,2) K1(-8.4,1.2) K2(-7.6,1.2) K3(-6.8,1.2) K4(-6,1.2) K5(-5.2,1.2) K6(-4.4,1.2) K7(-3.6,1.2) K9(-2,1.2) K10(-1.2,1.2) K11(-0.4,1.2) K12(0.4,1.2) K13(1.2,1.2) K14(2,1.2) K15(2.8,1.2) K17(4.4,1.2) K18(5.2,1.2) K19(6,1.2) K20(6.8,1.2) K21(7.6,1.2) K22(8.4,1.2) L1(-8.4,0.4) L2(-7.6,0.4) L3(-6.8,0.4) L4(-6,0.4) L5(-5.2,0.4) L6(-4.4,0.4) L8(-2.8,0.4) L9(-2,0.4) L10(-1.2,0.4) L11(-0.4,0.4) L12(0.4,0.4) L13(1.2,0.4) L14(2,0.4) L16(3.6,0.4) L17(4.4,0.4) L18(5.2,0.4) L19(6,0.4) L20(6.8,0.4) L21(7.6,0.4) L22(8.4,0.4) M1(-8.4,-0.4) M2(-7.6,-0.4) M3(-6.8,-0.4) M4(-6,-0.4) M5(-5.2,-0.4) M6(-4.4,-0.4) M7(-3.6,-0.4) M9(-2,-0.4) M10(-1.2,-0.4) M11(-0.4,-0.4) M12(0.4,-0.4) M13(1.2,-0.4) M14(2,-0.4) M15(2.8,-0.4) M17(4.4,-0.4) M18(5.2,-0.4) M19(6,-0.4) M20(6.8,-0.4) M21(7.6,-0.4) M22(8.4,-0.4) N1(-8.4,-1.2) N2(-7.6,-1.2) N3(-6.8,-1.2) N4(-6,-1.2) N5(-5.2,-1.2) N6(-4.4,-1.2) N8(-2.8,-1.2) N9(-2,-1.2) N10(-1.2,-1.2) N11(-0.4,-1.2) N12(0.4,-1.2) N13(1.2,-1.2) N14(2,-1.2) N16(3.6,-1.2) N17(4.4,-1.2) N18(5.2,-1.2) N19(6,-1.2) N20(6.8,-1.2) N21(7.6,-1.2) N22(8.4,-1.2) P1(-8.4,-2) P2(-7.6,-2) P3(-6.8,-2) P4(-6,-2) P5(-5.2,-2) P6(-4.4,-2) P7(-3.6,-2) P9(-2,-2) P10(-1.2,-2) P11(-0.4,-2) P12(0.4,-2) P13(1.2,-2) P14(2,-2) P15(2.8,-2) P17(4.4,-2) P18(5.2,-2) P19(6,-2) P20(6.8,-2) P21(7.6,-2) R1(-8.4,-2.8) R2(-7.6,-2.8) R3(-6.8,-2.8) R4(-6,-2.8) R5(-5.2,-2.8) R6(-4.4,-2.8) R8(-2.8,-2.8) R10(-1.2,-2.8) R12(0.4,-2.8) R14(2,-2.8) R16(3.6,-2.8) R17(4.4,-2.8) R18(5.2,-2.8) R19(6,-2.8) R20(6.8,-2.8) R21(7.6,-2.8) R22(8.4,-2.8) T1(-8.4,-3.6) T2(-7.6,-3.6) T3(-6.8,-3.6) T4(-6,-3.6) T5(-5.2,-3.6) T6(-4.4,-3.6) T7(-3.6,-3.6) T9(-2,-3.6) T11(-0.4,-3.6) T13(1.2,-3.6) T15(2.8,-3.6) T17(4.4,-3.6) T18(5.2,-3.6) T19(6,-3.6) T20(6.8,-3.6) T21(7.6,-3.6) T22(8.4,-3.6) U1(-8.4,-4.4) U2(-7.6,-4.4) U3(-6.8,-4.4) U4(-6,-4.4) U5(-5.2,-4.4) U6(-4.4,-4.4) U7(-3.6,-4.4) U8(-2.8,-4.4) U9(-2,-4.4) U10(-1.2,-4.4) U11(-0.4,-4.4) U12(0.4,-4.4) U13(1.2,-4.4) U14(2,-4.4) U15(2.8,-4.4) U16(3.6,-4.4) U17(4.4,-4.4) U18(5.2,-4.4) U19(6,-4.4) U20(6.8,-4.4) U21(7.6,-4.4) V1(-8.4,-5.2) V2(-7.6,-5.2) V3(-6.8,-5.2) V4(-6,-5.2) V5(-5.2,-5.2) V6(-4.4,-5.2) V7(-3.6,-5.2) V8(-2.8,-5.2) V9(-2,-5.2) V10(-1.2,-5.2) V11(-0.4,-5.2) V12(0.4,-5.2) V13(1.2,-5.2) V14(2,-5.2) V15(2.8,-5.2) V16(3.6,-5.2) V17(4.4,-5.2) V18(5.2,-5.2) V19(6,-5.2) V20(6.8,-5.2) V21(7.6,-5.2) V22(8.4,-5.2) W1(-8.4,-6) W2(-7.6,-6) W3(-6.8,-6) W4(-6,-6) W5(-5.2,-6) W6(-4.4,-6) W7(-3.6,-6) W8(-2.8,-6) W9(-2,-6) W10(-1.2,-6) W11(-0.4,-6) W12(0.4,-6) W13(1.2,-6) W14(2,-6) W15(2.8,-6) W16(3.6,-6) W17(4.4,-6) W18(5.2,-6) W19(6,-6) W20(6.8,-6) W21(7.6,-6) W22(8.4,-6) Y1(-8.4,-6.8) Y2(-7.6,-6.8) Y3(-6.8,-6.8) Y4(-6,-6.8) Y5(-5.2,-6.8) Y6(-4.4,-6.8) Y7(-3.6,-6.8) Y8(-2.8,-6.8) Y9(-2,-6.8) Y10(-1.2,-6.8) Y11(-0.4,-6.8) Y12(0.4,-6.8) Y13(1.2,-6.8) Y14(2,-6.8) Y15(2.8,-6.8) Y16(3.6,-6.8) Y17(4.4,-6.8) Y18(5.2,-6.8) Y19(6,-6.8) Y20(6.8,-6.8) Y21(7.6,-6.8) Y22(8.4,-6.8)
  silkscreen extent -9.15,-9 9,9.15, body extent -9,-9 9,9, height 1.28
ICC_P-WFBGA153_13X11P5_P050 [mm]
  round 0.23 smd mask+0.05: A1(-3.25,-3.25) A2(-3.25,-2.75) A3(-3.25,-2.25) A4(-3.25,-1.75) A5(-3.25,-1.25) A6(-3.25,-0.75) A7(-3.25,-0.25) A8(-3.25,0.25) A9(-3.25,0.75) A10(-3.25,1.25) A11(-3.25,1.75) A12(-3.25,2.25) A13(-3.25,2.75) A14(-3.25,3.25) B1(-2.75,-3.25) B2(-2.75,-2.75) B3(-2.75,-2.25) B4(-2.75,-1.75) B5(-2.75,-1.25) B6(-2.75,-0.75) B7(-2.75,-0.25) B8(-2.75,0.25) B9(-2.75,0.75) B10(-2.75,1.25) B11(-2.75,1.75) B12(-2.75,2.25) B13(-2.75,2.75) B14(-2.75,3.25) C1(-2.25,-3.25) C2(-2.25,-2.75) C3(-2.25,-2.25) C4(-2.25,-1.75) C5(-2.25,-1.25) C6(-2.25,-0.75) C7(-2.25,-0.25) C8(-2.25,0.25) C9(-2.25,0.75) C10(-2.25,1.25) C11(-2.25,1.75) C12(-2.25,2.25) C13(-2.25,2.75) C14(-2.25,3.25) D1(-1.75,-3.25) D2(-1.75,-2.75) D3(-1.75,-2.25) D4(-1.75,-1.75) D12(-1.75,2.25) D13(-1.75,2.75) D14(-1.75,3.25) E1(-1.25,-3.25) E2(-1.25,-2.75) E3(-1.25,-2.25) E5(-1.25,-1.25) E6(-1.25,-0.75) E7(-1.25,-0.25) E8(-1.25,0.25) E9(-1.25,0.75) E10(-1.25,1.25) E12(-1.25,2.25) E13(-1.25,2.75) E14(-1.25,3.25) F1(-0.75,-3.25) F2(-0.75,-2.75) F3(-0.75,-2.25) F5(-0.75,-1.25) F10(-0.75,1.25) F12(-0.75,2.25) F13(-0.75,2.75) F14(-0.75,3.25) G1(-0.25,-3.25) G2(-0.25,-2.75) G3(-0.25,-2.25) G5(-0.25,-1.25) G10(-0.25,1.25) G12(-0.25,2.25) G13(-0.25,2.75) G14(-0.25,3.25) H1(0.25,-3.25) H2(0.25,-2.75) H3(0.25,-2.25) H5(0.25,-1.25) H10(0.25,1.25) H12(0.25,2.25) H13(0.25,2.75) H14(0.25,3.25) J1(0.75,-3.25) J2(0.75,-2.75) J3(0.75,-2.25) J5(0.75,-1.25) J10(0.75,1.25) J12(0.75,2.25) J13(0.75,2.75) J14(0.75,3.25) K1(1.25,-3.25) K2(1.25,-2.75) K3(1.25,-2.25) K5(1.25,-1.25) K6(1.25,-0.75) K7(1.25,-0.25) K8(1.25,0.25) K9(1.25,0.75) K10(1.25,1.25) K12(1.25,2.25) K13(1.25,2.75) K14(1.25,3.25) L1(1.75,-3.25) L2(1.75,-2.75) L3(1.75,-2.25) L12(1.75,2.25) L13(1.75,2.75) L14(1.75,3.25) M1(2.25,-3.25) M2(2.25,-2.75) M3(2.25,-2.25) M4(2.25,-1.75) M5(2.25,-1.25) M6(2.25,-0.75) M7(2.25,-0.25) M8(2.25,0.25) M9(2.25,0.75) M10(2.25,1.25) M11(2.25,1.75) M12(2.25,2.25) M13(2.25,2.75) M14(2.25,3.25) N1(2.75,-3.25) N2(2.75,-2.75) N3(2.75,-2.25) N4(2.75,-1.75) N5(2.75,-1.25) N6(2.75,-0.75) N7(2.75,-0.25) N8(2.75,0.25) N9(2.75,0.75) N10(2.75,1.25) N11(2.75,1.75) N12(2.75,2.25) N13(2.75,2.75) N14(2.75,3.25) P1(3.25,-3.25) P2(3.25,-2.75) P3(3.25,-2.25) P4(3.25,-1.75) P5(3.25,-1.25) P6(3.25,-0.75) P7(3.25,-0.25) P8(3.25,0.25) P9(3.25,0.75) P10(3.25,1.25) P11(3.25,1.75) P12(3.25,2.25) P13(3.25,2.75) P14(3.25,3.25)
  silkscreen extent -6.78,-6.02 6.63,5.87, body extent -6.55,-5.8 6.55,5.8, height 1
ICC_VFBGA96_9x13_P080 [mm]
  round 0.4 smd mask+0.05: A1(-3.2,6) A2(-2.4,6) A3(-1.6,6) A7(1.6,6) A8(2.4,6) A9(3.2,6) B1(-3.2,5.2) B2(-2.4,5.2) B3(-1.6,5.2) B7(1.6,5.2) B8(2.4,5.2) B9(3.2,5.2) C1(-3.2,4.4) C2(-2.4,4.4) C3(-1.6,4.4) C7(1.6,4.4) C8(2.4,4.4) C9(3.2,4.4) D1(-3.2,3.6) D2(-2.4,3.6) D3(-1.6,3.6) D7(1.6,3.6) D8(2.4,3.6) D9(3.2,3.6) E1(-3.2,2.8) E2(-2.4,2.8) E3(-1.6,2.8) E7(1.6,2.8) E8(2.4,2.8) E9(3.2,2.8) F1(-3.2,2) F2(-2.4,2) F3(-1.6,2) F7(1.6,2) F8(2.4,2) F9(3.2,2) G1(-3.2,1.2) G2(-2.4,1.2) G3(-1.6,1.2) G7(1.6,1.2) G8(2.4,1.2) G9(3.2,1.2) H1(-3.2,0.4) H2(-2.4,0.4) H3(-1.6,0.4) H7(1.6,0.4) H8(2.4,0.4) H9(3.2,0.4) J1(-3.2,-0.4) J2(-2.4,-0.4) J3(-1.6,-0.4) J7(1.6,-0.4) J8(2.4,-0.4) J9(3.2,-0.4) K1(-3.2,-1.2) K2(-2.4,-1.2) K3(-1.6,-1.2) K7(1.6,-1.2) K8(2.4,-1.2) K9(3.2,-1.2) L1(-3.2,-2) L2(-2.4,-2) L3(-1.6,-2) L7(1.6,-2) L8(2.4,-2) L9(3.2,-2) M1(-3.2,-2.8) M2(-2.4,-2.8) M3(-1.6,-2.8) M7(1.6,-2.8) M8(2.4,-2.8) M9(3.2,-2.8) N1(-3.2,-3.6) N2(-2.4,-3.6) N3(-1.6,-3.6) N7(1.6,-3.6) N8(2.4,-3.6) N9(3.2,-3.6) P1(-3.2,-4.4) P2(-2.4,-4.4) P3(-1.6,-4.4) P7(1.6,-4.4) P8(2.4,-4.4) P9(3.2,-4.4) R1(-3.2,-5.2) R2(-2.4,-5.2) R3(-1.6,-5.2) R7(1.6,-5.2) R8(2.4,-5.2) R9(3.2,-5.2) T1(-3.2,-6) T2(-2.4,-6) T3(-1.6,-6) T7(1.6,-6) T8(2.4,-6) T9(3.2,-6)
  silkscreen extent -4.72,-6.55 4.55,6.73, body extent -4.55,-6.55 4.55,6.55, height 1
ICC_WFQFN44-EPAD_5X6_P040 [mm]
  rect 0.8x0.2 smd mask+0.05: 1(-2.45,2.2) 2(-2.45,1.8) 3(-2.45,1.4) 4(-2.45,1) 5(-2.45,0.6) 6(-2.45,0.2) 7(-2.45,-0.2) 8(-2.45,-0.6) 9(-2.45,-1) 10(-2.45,-1.4) 11(-2.45,-1.8) 12(-2.45,-2.2) 23(2.45,-2.2) 24(2.45,-1.8) 25(2.45,-1.4) 26(2.45,-1) 27(2.45,-0.6) 28(2.45,-0.2) 29(2.45,0.2) 30(2.45,0.6) 31(2.45,1) 32(2.45,1.4) 33(2.45,1.8) 34(2.45,2.2)
  rect 0.2x0.8 smd mask+0.05: 13(-1.8,-2.95) 14(-1.4,-2.95) 15(-1,-2.95) 16(-0.6,-2.95) 17(-0.2,-2.95) 18(0.2,-2.95) 19(0.6,-2.95) 20(1,-2.95) 21(1.4,-2.95) 22(1.8,-2.95) 35(1.8,2.95) 36(1.4,2.95) 37(1,2.95) 38(0.6,2.95) 39(0.2,2.95) 40(-0.2,2.95) 41(-0.6,2.95) 42(-1,2.95) 43(-1.4,2.95) 44(-1.8,2.95)
  rect 3.6x4.6 smd paste-1.8 mask+0.05: ep(0,0)
  silkscreen extent -2.5,-3 2.5,3, body extent -2.5,-3 2.5,3, height 0.81
IND_MURATA_DFE201612P [mm] "MCD-01491"
  rect 0.8x1.8 smd far side mask+0.05: 1(-0.8,0) 2(0.8,0)
  body extent -1.1,-0.9 1.1,0.9, height 1.2
R0402#1 [mm]
  rect 0.51x0.7 smd mask+0.05: 1(-0.45,0) 2(0.45,0)
  silkscreen extent 0,-0.3 0,0.3, body extent -0.52,-0.3 0.52,0.3, height 0.4
R0402#2 [mm]
  rect 0.51x0.7 smd far side mask+0.05: 1(-0.45,0) 2(0.45,0)
  body extent -0.52,-0.3 0.52,0.3, height 0.4
SWI_JIUBABA_C-TS-02H-2-5-B-V-T_R_BLUE [mm] "BLUE"
  rect 0.75x1 smd mask+0.05: 1(-2.225,0.75) 2(2.225,0.75) 3(-2.225,-0.75) 4(2.225,-0.75)
  silkscreen extent -1.85,-1.6 1.85,1.6, body extent -2.45,-1.6 2.45,1.6, height 2.6

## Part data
B1: library part MCD-00172, "Switch HW SMD blue"
C13 C14 C17 C19 C20 C21 C22 C23 C24 C25 C26 C27 C28 C30 C36 C40 C50 C68 C70 C72 C79: library part MCD-00006, "Capacitor, MLCC, 100nF, 16V, X7R, 10%, 0402, T=0.5mm"
C15 C16 C18 C31 C33 C35 C39 C46: library part MCD-00099, "Capacitor, MLCC, 10uF, 10V, X5R, 10%, 0603, T=0,8mm"
C29 C34 C38 C48: library part MCD-00100, "Capacitor, MLCC, 22uF, 6V3, X5R, 20%, 0603, T=0,8mm"
C32 C41 C45 C53 C54 C55 C56 C57 C58 C59 C60 C61 C62 C63 C64 C65 C66 C67 C75 C76 C80 C81 C82 C83 C84 C85 C86 C87 C90 C92 C93 C95 C96 C97: library part MCD-00095, "Capacitor, MLCC, 1uF, 25V, X5R, 10%, 0402, T=0,5mm"
C37 C42 C43: library part MCD-01823, "Capacitor,MLCC,2.2uF,6V3,X5R,10%,0402,T=0.5"
C44 C74: library part MCD-00011, "Capacitor, MLCC, 10nF, 16V, X7R, 10%, 0402, T=0.5mm"
C47 C49 C51 C52: library part MCD-01356, "Capacitor, MLCC, 4.7uF, 6V3, X5R, 20%, 0402, T=0,5mm"
C69 C71 C73: library part MCD-00012, "Capacitor, MLCC, 2.2uF, 10V, X5R, 10%, 0603, T=0,8mm"
C91 C94: library part MCD-00198, "Capacitor, MLCC, 1nF, 16V, X7R, 10%, 0402, T=0.5mm"
L1 L2 L3 L4: library part MCD-01491, "Inductors 1.0uH 54mOhms3.3A +/-20% 2016"
R26 R27: library part MCD-00120, "Resistor,240R,0402,1%,1/16W"
R28: library part MCD-00067, "Resistor,100R,0402,1%,1/16W"
R29 R30 R40: library part MCD-00053, "Resistor,10K,0402,1%,1/16W"
R37 R38: library part MCD-00068, "Resistor,1K5,0402,1%,1/16W"
R43: library part MCD-00063, "Resistor,47K,0402,1%,1/16W"
R96: library part MCD-00052, "Resistor,0R,0402,5%,1/16W"
U1: library part MCD-00618, "MPU LFBGA18x18 with crypto"
U2: library part MCD-01811, "Memory,DDR3L,4Gb,256Mbx16,933Mhz,1V35,TFBGA"
U4: library part MCD-01650, "ST PMIC:  4 step-down + 1 advanced boost SMPS, 6 LDOs, 2 pwr switches, DDR Vref, NVM option 'A' for IO@3.3V"
U5: library part MCD-00110, "Memory,e-MMC,4GB,3V3,WFBGA,153pins"

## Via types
v1: diameter 0.4, hole 0.2, Top Layer to Bottom Layer, tented both sides, 295 vias
v2: diameter 0.6, hole 0.3, Top Layer to Bottom Layer, tented both sides, 93 vias
v3: diameter 0.4, hole 0.2, Top Layer to Signal Layer 1, tented top, 2 vias

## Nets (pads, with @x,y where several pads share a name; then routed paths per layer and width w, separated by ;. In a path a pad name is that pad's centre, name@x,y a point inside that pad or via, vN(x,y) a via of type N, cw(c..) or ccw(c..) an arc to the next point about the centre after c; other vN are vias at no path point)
3V3: C32.2 C48.2 C72.2 C73.2 L4.2 U4.22 U4.27 U5.E6 U5.F5 U5.J10 U5.K9 | length 48.6
  Top Layer w0.175: U5.J10@27.15,88.475 U5.K9@27.65,88.975 v1(27.65,89.45) ; U5.E6@29.15,86.475 U5.F5@29.65,86.975 v1(30.075,86.975)
  Top Layer w0.2: 9.5,82.85 9.85,83.2 U4.22@10.05,83.2 ; v1(12.2,81.25) 12.2,81.85 12.4,82.05 U4.27@12.4,82.55
  Top Layer w0.3: C32.2@7.1,80.5 v1(7.1,80.85) 7.1,81.45 7.5,81.85 8.5,81.85 9.5,82.85
  Top Layer w0.5: C48.2@10.125,77.55 v1(10.8,77.55)
  Top Layer w0.6: C48.2@10.125,77.55 L4.2@10.125,78.75
  Signal Layer 4 w0.3: v1(7.1,80.85) 10.4,77.55 v1(10.8,77.55)
  Bottom Layer w0.1: C73.2@26.8,89.575 C73.2@26.925,89.45 ; v1@30,87.05 v1(30.075,86.975)
  Bottom Layer w0.3: v1(12.2,81.25) 11.525,80.575 11.525,77.75 11.325,77.55 v1(10.8,77.55) 10.8,81 11.925,82.125 15.05,82.125 15.625,81.55 19.9,81.55 23.625,85.275 23.625,86.4 C73.2@26.8,89.575 ; C73.2@26.925,89.45 v1(27.65,89.45) 28.1,89.45 C72.2@30,87.55 v1@30,87.05
5V_VIN: C18.2 C31.2 C33.2 C39.2 C41.2 C51.1 R43.2 U4.8 U4.12 U4.19 U4.24 U4.28 U4.36 U4.37 | length 15.1
  Top Layer w0.09: v1(12.8,81.15) U4.28@12.8,82.55
  Top Layer w0.12: R43.2@18.25,81.95 R43.2@18.3,82
  Top Layer w0.2: C39.2@9.3,80.45 9.525,80.675 9.525,80.875 10.1,81.45 10.6,81.45 11.2,82.05 U4.24@11.2,82.55 ; 9.35,84.4 U4.19@10.05,84.4 ; C31.2@12.4,80.45 12.8,80.85 v1(12.8,81.15) ; U4.8@12.4,87.45 12.4,88.85 v1(12.2,89.05) 12.2,89.55 C33.2@12.4,89.75 ; U4.36@15.95,83.6 16.625,83.6 v1(16.8,83.775) ; U4.37@15.95,84 16.575,84 v1(16.8,83.775) ; R43.2@18.3,82 C51.1@18.3,82.75 18.225,82.825 v1(17.75,82.825) v1(16.8,83.775)
  Top Layer w0.3: C41.2@7.65,83.95 v1(8.2,83.95) 8.65,84.4 9.35,84.4
  other v1: 9.1,81.05 9.5,87.85
DDR_A0: U1.K19 U2.N3 | length 31.4
  Top Layer w0.12: v1(37.8,63.9) U1.K19@38.2,63.5 ; U2.N3@51.73,60.95 v1(52.13,61.35)
  Bottom Layer w0.12: v1(37.8,63.9) 38.091,63.9 38.531,64.34 38.749,64.34 38.96,64.551 38.96,64.764 39.375,65.179 39.375,65.527 40.205,66.357 40.205,66.745 41.035,67.575 41.035,69.502 41.423,69.89 41.598,69.89 42.438,70.73 46.615,70.73 46.725,70.62 46.725,70.395 46.6,70.27 46.6,70.129 47.424,69.304 47.644,69.304 47.86,69.52 48.065,69.52 48.135,69.45 48.135,69.148 48.389,68.894 48.389,68.734 48.135,68.479 48.135,65.444 46.945,64.254 46.945,61.754 47.949,60.75 51.58,60.75 v1@52.13,61.3
DDR_A1: U1.M18 U2.P7 | length 31.8
  Top Layer w0.12: v1(37,62.3) U1.M18@37.4,61.9 ; v1(50.53,57.35) U2.P7@50.93,57.75
  Bottom Layer w0.12: v1(37,62.3) 37.4,61.9 37.4,61.125 37.635,60.89 38.119,60.89 39.159,59.85 39.398,59.85 41.65,57.598 41.65,54.355 41.955,54.05 41.955,53.484 42.475,52.964 42.475,52.165 42.6,52.04 42.81,52.04 42.89,52.12 42.89,52.885 43.015,53.01 44.02,53.01 44.125,52.905 44.125,52.11 44.195,52.04 44.465,52.04 44.54,52.115 44.54,54.627 44.888,54.975 45.695,54.975 45.79,54.88 45.79,53.44 45.87,53.36 46.085,53.36 46.205,53.48 46.205,56.683 47.232,57.71 50.17,57.71 v1(50.53,57.35)
DDR_A2: U1.J18 U2.P3 | length 31.3
  Top Layer w0.12: U1.J18@37.4,64.3 v1(37.8,64.7) ; U2.P3@50.93,60.9 v1@51.33,61.3
  Bottom Layer w0.12: v1(37.8,64.7) 38.2,65.1 38.2,66.113 38.96,66.873 38.96,67.261 39.79,68.096 39.79,70.277 41.488,71.975 48.029,71.975 49.685,70.319 49.685,68.269 49.38,67.964 49.38,64.495 49.146,64.261 48.712,64.261 48.19,63.738 48.19,62.27 48.742,61.718 50.962,61.718 v1(51.33,61.35)
DDR_A3: U1.J19 U2.N2 | length 31.1
  Top Layer w0.12: U1.J19@38.2,64.3 v1(38.6,64.7) ; U2.N2@51.73,61.7 v1@52.13,62.1
  Bottom Layer w0.12: v1(38.6,64.7) 38.6,64.991 38.96,65.351 38.96,65.699 39.79,66.529 39.79,66.917 40.62,67.747 40.62,69.739 41.186,70.305 41.426,70.305 42.266,71.145 47.01,71.145 47.14,71.015 47.14,70.176 47.381,69.935 48.38,69.935 48.55,69.765 48.55,69.32 48.855,69.015 48.855,68.613 48.55,68.308 48.55,65.272 47.36,64.082 47.36,61.926 48.296,60.99 51.479,60.99 51.72,61.231 51.72,61.69 v1@52.13,62.1
  other v1: 52.13,62.15
DDR_A4: U1.T18 U2.P8 | length 30
  Top Layer w0.12: v1(37,58.3) U1.T18@37.4,58.7 ; v1(50.53,55.75) 50.53,56.55 U2.P8@50.93,56.95
  Bottom Layer w0.12: v1(37,58.3) 36.62,57.92 36.62,57.25 37.56,56.31 37.94,56.31 38.33,55.92 38.33,49.907 39.517,48.72 48.75,48.72 50.53,50.5 v1@50.53,55.695
DDR_A5: U1.H19 U2.P2 | length 30.6
  Top Layer w0.1: v1(50.53,61.35) U2.P2@50.93,61.75
  Top Layer w0.12: U1.H19@38.2,65.1 v1(38.6,65.5)
  Bottom Layer w0.12: v1@38.727,65.517 38.71,65.5 v1(38.6,65.5) 38.6,65.926 39.375,66.701 39.375,67.089 40.205,67.919 40.205,70.105 40.375,70.275 40.569,70.275 40.697,70.403 40.697,70.596 41.161,71.06 41.354,71.06 41.505,71.211 41.505,71.38 41.685,71.56 47.857,71.56 48.34,71.077 48.34,70.86 48.25,70.77 47.69,70.77 47.555,70.635 47.555,70.445 47.65,70.35 49.067,70.35 49.27,70.147 49.27,69.94 48.985,69.655 48.985,69.472 49.27,69.187 49.27,68.441 48.965,68.136 48.965,65.1 47.775,63.91 47.775,62.098 48.531,61.343 v1@50.36,61.343
DDR_A6: U1.U19 U2.R8 | length 29
  Top Layer w0.12: v1(37.8,57.5) U1.U19@38.2,57.9 ; v1(49.73,55.75) 49.73,56.55 U2.R8@50.13,56.95
  Bottom Layer w0.12: v1(37.8,57.5) 38.226,57.5 39.16,56.566 39.16,50.251 39.861,49.55 48.406,49.55 49.7,50.844 49.7,52.815 49.45,53.065 49.12,53.065 48.945,53.24 48.945,53.65 49.095,53.8 49.525,53.8 49.7,53.975 49.7,54.2 49.475,54.425 48.973,54.425 48.555,54.843 48.555,55.219 49.086,55.75 v1(49.73,55.75)
DDR_A7: U1.F18 U2.R2 | length 29.5
  Top Layer w0.12: v1(37,66.3) U1.F18@37.4,66.7 ; U2.R2@50.13,61.75 v1(50.53,62.15)
  Bottom Layer w0.12: v1(37,66.3) 37,66.565 37.36,66.925 37.36,67.345 38.24,68.225 38.24,70.488 40.972,73.22 48.545,73.22 50.93,70.835 50.93,62.5 v1@50.53,62.1
DDR_A8: U1.U18 U2.T8 | length 29
  Top Layer w0.12: v1(37,57.5) U1.U18@37.4,57.9 ; v1@48.93,55.07 48.93,56.55 U2.T8@49.33,56.95
  Bottom Layer w0.12: v1@37.02,57.5 v1(37,57.5) 37.415,57.085 38.054,57.085 38.745,56.394 38.745,50.079 39.689,49.135 48.578,49.135 50.115,50.672 50.115,52.987 49.92,53.182 49.92,53.608 50.115,53.803 50.115,54.57 49.845,54.84 49.145,54.84 v1(48.915,55.07)
DDR_A9: U1.H18 U2.R3 | length 31.7
  Top Layer w0.12: U1.H18@37.4,65.1 v1(37.8,65.5) ; v1(49,62.15) 48.97,62.12 48.97,61.601 49.226,61.345 49.735,61.345 U2.R3@50.13,60.95
  Bottom Layer w0.12: v1(37.8,65.5) 37.5,65.5 37.39,65.61 37.39,66.399 37.78,66.789 37.78,67.26 38.96,68.44 38.96,70.621 41.144,72.805 48.373,72.805 50.515,70.663 50.515,63.369 50.125,62.979 50.125,62.28 49.995,62.15 v1(49,62.15)
DDR_A10: U1.N18 U2.L7 | length 32.7
  Top Layer w0.12: v1(37,61.5) U1.N18@37.4,61.1 ; v1(52.93,57.35) U2.L7@53.33,57.75
  Bottom Layer w0.12: v1(37,61.5) 36.7,61.2 36.7,60.41 36.6,60.31 36.6,59.775 36.88,59.495 37.992,59.495 40.405,57.082 40.405,53.839 40.71,53.534 40.71,53.236 40.405,52.931 40.405,50.92 40.53,50.795 47.295,50.795 47.45,50.95 47.45,56.168 48.047,56.765 49.9,56.765 49.985,56.85 52.43,56.85 v1(52.93,57.35)
DDR_A11: U1.P19 U2.R7 | length 31.2
  Top Layer w0.12: v1(37.8,59.9) U1.P19@38.2,60.3 ; v1(49.73,57.35) U2.R7@50.13,57.75
  Bottom Layer w0.12: v1(37.8,59.9) 38.064,59.9 39.083,58.882 39.192,58.882 40.82,57.254 40.82,54.011 41.125,53.706 41.125,53.064 40.82,52.759 40.82,51.31 40.92,51.21 41.167,51.21 41.23,51.273 41.23,52.53 41.37,52.67 41.58,52.67 41.645,52.605 41.645,51.315 41.75,51.21 43.154,51.21 43.404,51.46 43.526,51.46 43.776,51.21 46.075,51.21 46.195,51.33 46.195,52.46 46.265,52.53 46.545,52.53 46.615,52.46 46.615,51.34 46.745,51.21 46.935,51.21 47.035,51.31 47.035,56.34 47.685,56.99 49.37,56.99 v1(49.73,57.35)
DDR_A12: U1.N19 U2.N7 | length 32.2
  Top Layer w0.12: v1(37.8,61.5) U1.N19@38.2,61.1 ; v1(51.33,57.35) U2.N7@51.73,57.75
  Bottom Layer w0.12: v1(37.8,61.5) 38.075,61.5 39.235,60.34 39.256,60.34 39.331,60.265 39.569,60.265 42.065,57.769 42.065,54.527 42.37,54.222 42.37,53.656 42.601,53.425 44.03,53.425 44.125,53.52 44.125,54.685 44.039,54.771 43.696,54.771 43.523,54.943 43.523,55.102 43.607,55.185 44.025,55.185 44.125,55.285 44.125,56.325 44.02,56.43 43.405,56.43 43.315,56.52 43.315,56.76 43.405,56.85 43.985,56.85 44.125,56.99 44.125,58 44.27,58.145 44.388,58.145 44.545,57.988 44.545,55.495 44.65,55.39 45.67,55.39 45.79,55.51 45.79,57.54 45.93,57.68 46.615,57.68 46.89,57.955 50.725,57.955 v1(51.33,57.35)
DDR_A13: U1.G18 U2.T3 | length 29.9
  Top Layer w0.12: U1.G18@37.4,65.9 v1(37.8,66.3) ; v1(48.55,62.47) 48.55,61.434 48.765,61.219 48.765,61.1 48.915,60.95 U2.T3@49.33,60.95
  Bottom Layer w0.12: v1(37.8,66.3) 38.24,66.74 38.24,67.249 38.642,67.651 38.763,67.651 ; 38.763,67.657 39.375,68.268 39.375,70.449 41.316,72.39 48.201,72.39 50.1,70.491 50.1,68.097 49.795,67.792 49.795,64.04 49.601,63.846 48.884,63.846 48.685,63.646 48.685,63.45 48.9,63.235 49.079,63.235 49.315,62.999 49.315,62.65 49.175,62.51 48.59,62.51 v1(48.55,62.47)
DDR_A14: U1.P18 U2.T7 | length 31.7
  Top Layer w0.12: v1(37,59.9) U1.P18@37.4,60.3 ; v1(48.93,57.35) U2.T7@49.33,57.75
  Bottom Layer w0.12: v1(37,59.9) 37.005,59.9 37.49,60.385 38.095,60.385 39.045,59.435 39.226,59.435 41.235,57.426 41.235,54.183 41.54,53.878 41.54,53.23 41.685,53.085 41.752,53.085 42.06,52.777 42.06,51.78 42.215,51.625 42.982,51.625 43.305,51.948 43.305,52.51 43.39,52.595 43.625,52.595 43.71,52.51 43.71,51.863 43.948,51.625 44.845,51.625 44.955,51.735 44.955,54.455 45.06,54.56 45.25,54.56 45.375,54.435 45.375,51.715 45.465,51.625 45.615,51.625 45.78,51.79 45.78,52.642 46.083,52.945 46.365,52.945 46.62,53.2 46.62,56.511 47.459,57.35 v1(48.93,57.35)
DDR_A15: U1.M19 U2.M7 | length 31.8
  Top Layer w0.12: U1.M19@38.2,61.9 v1(38.6,61.5) ; v1(52.15,57.35) 52.53,57.73 U2.M7@52.53,57.75
  Bottom Layer w0.12: v1(38.6,61.5) 38.891,61.5 39.251,61.14 39.485,61.14 39.935,60.69 39.935,60.486 42.48,57.941 42.48,54.699 42.785,54.394 42.785,53.97 42.915,53.84 43.54,53.84 43.71,54.01 43.71,54.165 43.23,54.645 43.23,54.65 43.108,54.772 43.108,55.341 43.425,55.658 43.425,55.823 42.9,56.348 42.9,56.932 43.233,57.265 43.525,57.265 43.71,57.45 43.71,57.76 43.52,57.95 43.16,57.95 43.065,58.045 43.065,58.375 43.25,58.56 44.56,58.56 44.96,58.16 44.96,55.93 45.085,55.805 45.23,55.805 45.375,55.95 45.375,57.885 45.585,58.095 46.468,58.095 46.583,58.21 51.29,58.21 v1(52.15,57.35) v1@52.15,57.345
DDR_BA0: U1.K20 U2.M2 | length 30.4
  Top Layer w0.12: v1(38.6,63.1) U1.K20@39,63.5 ; U2.M2@52.53,61.75 52.53,61.675 v1(52.855,61.35)
  Bottom Layer w0.12: v1(38.6,63.1) 38.6,63.12 38.81,63.33 38.81,63.48 38.96,63.63 38.96,63.964 39.43,64.434 39.43,64.647 39.79,65.007 39.79,65.356 40.62,66.186 40.62,66.573 41.45,67.403 41.45,69.33 41.595,69.475 41.77,69.475 42.61,70.315 45.827,70.315 47.72,68.422 47.72,65.616 46.53,64.426 46.53,61.582 47.612,60.5 51.89,60.5 52.74,61.35 v1(52.855,61.35)
DDR_BA1: U1.R18 U2.N8 | length 31.1
  Top Layer w0.12: v1(37,59.1) U1.R18@37.4,59.5 ; v1(51.33,55.75) 51.33,56.55 U2.N8@51.73,56.95
  Bottom Layer w0.12: v1(37,59.1) 37.405,58.695 37.405,58.045 37.535,57.915 38.398,57.915 39.575,56.738 39.575,50.423 40.033,49.965 48.234,49.965 49.285,51.016 49.285,52.27 48.53,53.025 48.53,54.281 48.28,54.531 48.28,55.824 48.566,56.11 50.97,56.11 v1(51.33,55.75)
DDR_BA2: U1.K18 U2.M3 | length 30.5
  Top Layer w0.12: U1.K18@37.4,63.5 v1(37.8,63.1) ; U2.M3@52.53,60.95 52.53,60.895 v1(52.855,60.57)
  Bottom Layer w0.12: v1(37.8,63.1) 38.21,62.69 38.74,62.69 39.04,62.99 39.04,63.249 39.375,63.584 39.375,63.792 39.845,64.262 39.845,64.475 40.205,64.835 40.205,65.184 41.035,66.014 41.035,66.401 41.865,67.231 41.865,68.513 43.177,69.825 45.601,69.825 47.305,68.121 47.305,65.788 46.115,64.598 46.115,61.411 47.268,60.258 52.038,60.258 52.35,60.57 v1(52.855,60.57)
DDR_CASN: U1.M22 U2.K3 | length 28.8
  Top Layer w0.12: U1.M22@40.6,61.9 40.95,62.25 v1(41.05,62.25) ; U2.K3@54.13,60.95 54.205,60.95 v1@54.53,60.625
  Bottom Layer w0.12: v1@41.065,62.25 41.065,62.548 42.28,63.763 42.28,64.324 43.11,65.154 43.11,65.542 43.94,66.372 43.94,67.285 44.053,67.398 44.203,67.398 45.02,66.581 45.02,66.437 43.645,65.062 43.645,64.88 44.04,64.485 44.04,60.551 45.602,58.989 52.758,58.989 53.037,58.71 54.06,58.71 55.035,59.685 55.035,60.065 v1(54.53,60.57)
DDR_CKE: R30.2 U1.R19 U2.K9 | length 31.5
  Top Layer w0.12: v1(37.8,59.1) U1.R19@38.2,59.5 ; v1@53.735,55.75 53.735,55.755 U2.K9@54.13,56.15
  Bottom Layer w0.12: v1(37.8,59.1) 39.99,56.91 39.99,50.595 40.205,50.38 47.605,50.38 47.865,50.64 47.865,55.996 48.304,56.435 53.05,56.435 v1@53.735,55.75 ; v1(53.73,55.75) 54.495,54.985 R30.2@54.56,54.985
DDR_CLK_N: R28.1 U1.N21 U2.K7 | length 32.5
  Top Layer w0.1: U1.N21@39.8,61.1 v1(40.2,61.5) ; U2.K7@54.13,57.75 v1(54.53,58.15)
  Bottom Layer w0.1: v1(40.2,61.5) 40.37,61.33 40.54,61.33 41.095,61.885 41.815,61.885 41.9,61.97 41.9,62.81 42.685,63.595 42.685,64.055 42.965,64.335 43.335,64.335 43.635,64.035 43.635,62.76 43.405,62.53 43.405,62.18 43.635,61.95 43.635,61.46 43.09,60.915 41.395,60.915 41.34,60.86 41.34,60.58 41.402,60.518 43.5,60.518 43.85,60.168 43.85,59.83 43.61,59.59 42.189,59.59 42.079,59.48 42.079,59.254 42.139,59.195 44.823,59.195 45.288,58.73 52.62,58.73 53.475,57.875 54.255,57.875 v1(54.53,58.15) 54.81,57.87 55.665,57.87 56,58.205 R28.1@56.12,58.205
DDR_CLK_P: R28.2 U1.N20 U2.J7 | length 33.4
  Top Layer w0.1: U1.N20@39,61.1 v1(39.4,61.5) ; v1(54.53,57.35) U2.J7@54.93,57.75
  Bottom Layer w0.1: v1@39.41,61.49 39.673,61.49 40.063,61.1 40.635,61.1 41.19,61.655 41.91,61.655 42.13,61.875 42.13,62.715 42.915,63.5 42.915,63.96 43.06,64.105 43.24,64.105 43.405,63.94 43.405,62.855 43.175,62.625 43.175,62.085 43.405,61.855 43.405,61.555 42.995,61.145 41.3,61.145 41.11,60.955 41.11,60.485 41.307,60.288 43.405,60.288 43.62,60.073 43.62,59.925 43.515,59.82 42.094,59.82 41.849,59.575 41.849,59.159 42.043,58.965 44.728,58.965 45.193,58.5 52.525,58.5 53.38,57.645 54.235,57.645 v1(54.53,57.35) 54.82,57.64 55.635,57.64 55.97,57.305 R28.2@56.12,57.305
DDR_CSN: U1.L18 U2.L2 | length 32.4
  Top Layer w0.12: U1.L18@37.4,62.7 v1(37.8,62.3) ; U2.L2@53.395,61.75 U2.L2@53.33,61.75 v1(53.73,61.35)
  Bottom Layer w0.12: v1(37.8,62.3) 38.21,61.89 38.699,61.89 39.04,62.231 39.04,62.449 39.31,62.719 39.624,62.719 39.76,62.855 39.76,63.003 41.035,64.278 41.035,64.84 41.865,65.67 41.865,66.058 42.695,66.888 42.695,68.169 43.521,68.995 45.257,68.995 46.475,67.777 46.475,66.131 45.285,64.941 45.285,61.067 46.623,59.729 53.019,59.729 53.44,60.15 53.44,61.06 v1(53.73,61.35)
DDR_DQ0: U1.E21 U2.B8 | length 33.4
  Top Layer w0.12: U1.E21@39.805,67.495 40.114,67.495 40.429,67.18 59.902,67.18 63.36,63.722 63.36,59.138 61.567,57.345 61.175,57.345 60.78,56.95 U2.B8@60.53,56.95
DDR_DQ1: U1.F21 U2.C8 | length 32.2
  Top Layer w0.12: U1.F21@39.8,66.7 40.04,66.46 42.695,66.46 42.805,66.35 59.558,66.35 62.72,63.188 62.72,59.672 60.929,57.881 60.929,57.539 60.72,57.33 60.11,57.33 U2.C8@59.73,56.95
DDR_DQ2: U1.H21 U2.C2 | length 32.3
  Top Layer w0.12: U1.H21@39.8,65.1 39.8,64.745 39.925,64.62 39.933,64.62 39.993,64.56 40.323,64.56 40.483,64.4 41.15,64.4 41.495,64.055 42.864,64.055 43.48,63.439 43.48,61.125 43.559,61.046 43.729,61.046 44.185,61.502 44.65,61.502 45.135,61.017 45.135,60.195 44.86,59.92 44.465,59.92 44.275,59.73 44.275,59.457 44.638,59.094 44.801,59.094 45.565,59.858 45.565,61.172 45.898,61.505 47.17,61.505 47.305,61.64 47.305,62.934 48.13,63.759 48.13,63.99 48.205,64.065 53.519,64.065 53.775,63.809 54.335,63.809 54.591,64.065 58.164,64.065 58.247,63.982 58.247,63.515 58.357,63.405 58.824,63.405 59.1,63.129 59.1,62.889 59.325,62.664 59.325,62.42 59.73,62.015 U2.C2@59.73,61.75
DDR_DQ3: U1.E20 U2.A7 | length 32.2
  Top Layer w0.12: U1.E20@39,67.5 39.42,67.08 40.007,67.08 40.322,66.765 59.73,66.765 63.04,63.455 63.04,59.405 61.385,57.75 U2.A7@61.33,57.75
DDR_DQ4: U1.J21 U2.C3 | length 32.7
  Top Layer w0.12: U1.J21@39.8,64.3 40.08,64.3 40.285,64.095 40.96,64.095 41.415,63.64 42.692,63.64 43.065,63.267 43.065,60.668 43.258,60.475 43.745,60.475 44.357,61.087 44.478,61.087 44.7,60.865 44.7,60.742 43.86,59.902 43.86,59.285 44.466,58.679 44.973,58.679 45.98,59.686 45.98,61 46.07,61.09 46.32,61.09 46.4,61.01 46.4,60.515 46.49,60.425 46.719,60.425 47.72,61.426 47.72,62.762 48.608,63.65 53.347,63.65 53.603,63.394 54.507,63.394 54.763,63.65 57.561,63.65 58.55,62.661 58.55,62.26 58.66,62.15 59.039,62.15 59.32,61.869 59.32,61.64 59.73,61.23 U2.C3@59.73,60.95
DDR_DQ5: U1.H20 U2.A3 | length 34
  Top Layer w0.12: U1.H20@39,65.1 39.48,64.62 39.48,64.167 39.667,63.98 39.845,63.98 40.005,63.82 40.745,63.82 41.34,63.225 42.52,63.225 42.65,63.095 42.65,60.371 43.445,59.576 43.445,59.113 44.294,58.264 45.145,58.264 48.135,61.254 48.135,62.589 48.781,63.235 53.175,63.235 53.431,62.979 54.679,62.979 54.935,63.235 56.525,63.235 56.89,62.87 56.89,62.285 57.065,62.11 57.565,62.11 57.73,61.945 57.73,61.505 57.885,61.35 58.239,61.35 58.535,61.054 58.535,59.69 58.752,59.473 59.63,59.473 60.248,60.09 60.599,60.09 60.895,60.386 60.895,60.515 U2.A3@61.33,60.95
DDR_DQ6: U1.H22 U2.A2 | length 31.7
  Top Layer w0.12: U1.H22@40.6,65.1 40.765,65.265 41.37,65.265 41.75,64.885 43.208,64.885 44.31,63.783 44.31,62.417 44.395,62.332 44.627,62.332 44.735,62.44 44.735,63.675 44.83,63.77 45.015,63.77 45.155,63.63 45.155,62.4 45.23,62.325 45.505,62.325 45.575,62.395 45.575,63.65 45.655,63.73 45.915,63.73 46.015,63.63 46.015,62.395 46.075,62.335 46.36,62.335 46.475,62.45 46.475,63.278 47.3,64.103 47.3,64.582 47.613,64.895 58.508,64.895 59.296,64.106 59.744,64.106 60.353,63.498 ; 60.353,63.496 60.705,63.144 60.705,62.911 60.92,62.696 60.92,62.16 U2.A2@61.33,61.75
DDR_DQ7: U1.G19 U2.D7 | length 33.5
  Top Layer w0.09: 39.39,65.775 39.57,65.595 40.31,65.595 40.325,65.58
  Top Layer w0.12: U1.G19@38.2,65.9 38.52,66.22 39.133,66.22 39.39,65.963 39.39,65.775 ; 40.325,65.58 41.515,65.58 41.795,65.3 43.379,65.3 44.494,64.185 46.796,64.185 46.885,64.274 46.885,64.754 47.441,65.31 58.885,65.31 58.985,65.21 58.985,65.005 59.468,64.521 59.916,64.521 60.764,63.674 60.965,63.674 61.7,62.939 61.7,60.52 60.855,59.675 60.42,59.675 59.802,59.058 59.043,59.058 58.93,58.945 U2.D7@58.93,57.75
DDR_DQ8: U1.N22 U2.G2 | length 20.6
  Top Layer w0.12: U1.N22@40.6,61.1 41.582,61.1 41.96,60.722 41.96,60.474 43.03,59.404 43.03,58.941 44.588,57.383 45.441,57.383 45.573,57.515 45.573,58.105 48.058,60.59 52.325,60.59 52.705,60.21 54.75,60.21 55.33,60.79 55.33,61.135 55.585,61.39 55.895,61.39 56.245,61.74 56.53,61.74 U2.G2@56.53,61.75
DDR_DQ9: U1.R21 U2.F2 | length 22.8
  Top Layer w0.12: U1.R21@39.8,59.5 40.12,59.82 41.015,59.82 41.205,59.63 41.631,59.63 42.2,59.061 42.2,58.597 44.247,56.55 44.705,56.55 ; 44.708,56.553 44.711,56.55 46.33,56.55 46.403,56.623 46.403,57.761 48.486,59.844 52.269,59.844 52.413,59.7 55.755,59.7 56.13,60.075 56.13,61.059 56.421,61.35 56.93,61.35 U2.F2@57.33,61.75
DDR_DQ10: U1.P21 U2.H3 | length 21.5
  Top Layer w0.12: U1.P21@39.8,60.3 39.855,60.355 39.855,60.582 40.073,60.8 40.305,60.8 40.42,60.685 40.42,60.425 40.6,60.245 40.835,60.245 41.03,60.44 41.03,60.565 41.15,60.685 41.41,60.685 41.545,60.55 41.545,60.302 42.615,59.232 42.615,58.769 44.419,56.965 44.533,56.965 44.536,56.968 44.88,56.968 44.882,56.965 45.89,56.965 45.988,57.063 45.988,57.933 48.253,60.198 52.312,60.198 52.545,59.965 55.23,59.965 55.73,60.465 U2.H3@55.73,60.95
DDR_DQ11: U1.T20 U2.H8 | length 22.3
  Top Layer w0.12: U1.T20@39,58.7 39.395,58.305 39.395,57.695 39.59,57.5 39.97,57.5 40.28,57.19 40.28,56.967 40.568,56.679 40.781,56.679 43.8,53.66 45.307,53.66 45.722,54.075 45.99,54.075 46.405,53.66 47.865,53.66 47.93,53.725 47.93,53.93 48.075,54.075 48.36,54.075 48.445,53.99 48.445,53.74 48.525,53.66 53.595,53.66 54.03,54.095 54.03,54.741 55.335,56.046 55.335,56.555 U2.H8@55.73,56.95
DDR_DQ12: U1.V20 U2.F8 | length 22.6
  Top Layer w0.12: U1.V20@39,57.1 39.4,56.7 39.4,56.247 39.747,55.9 39.853,55.9 40.28,55.473 40.28,55.367 40.542,55.105 41.181,55.105 43.456,52.83 53.939,52.83 56.925,55.816 56.925,56.545 U2.F8@57.33,56.95
DDR_DQ13: U1.R20 U2.E3 | length 23.8
  Top Layer w0.12: U1.R20@39,59.5 39.39,59.11 39.843,59.11 40.19,58.763 40.19,58.657 40.487,58.36 40.966,58.36 43.816,55.51 46.79,55.51 47.625,56.345 47.625,57.513 48.963,58.85 53.375,58.85 53.565,59.04 56.265,59.04 58.13,60.905 U2.E3@58.13,60.95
